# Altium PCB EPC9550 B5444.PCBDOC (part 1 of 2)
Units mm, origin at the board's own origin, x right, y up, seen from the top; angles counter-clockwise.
Board outline 50 x 37 mm, 8 copper layers (Top Layer, Mid-Layer 1, Mid Layer 2 (Gnd), Mid-Layer 3 (Gnd), Mid-Layer 4 (54V), Mid Layer 5 (54V), Mid-Layer 6, Bottom Layer), stack 1.444 mm thick; 107 components, 61 nets, 523 pads, 597 vias.
Unrouted connection lines stored in the file: 17.
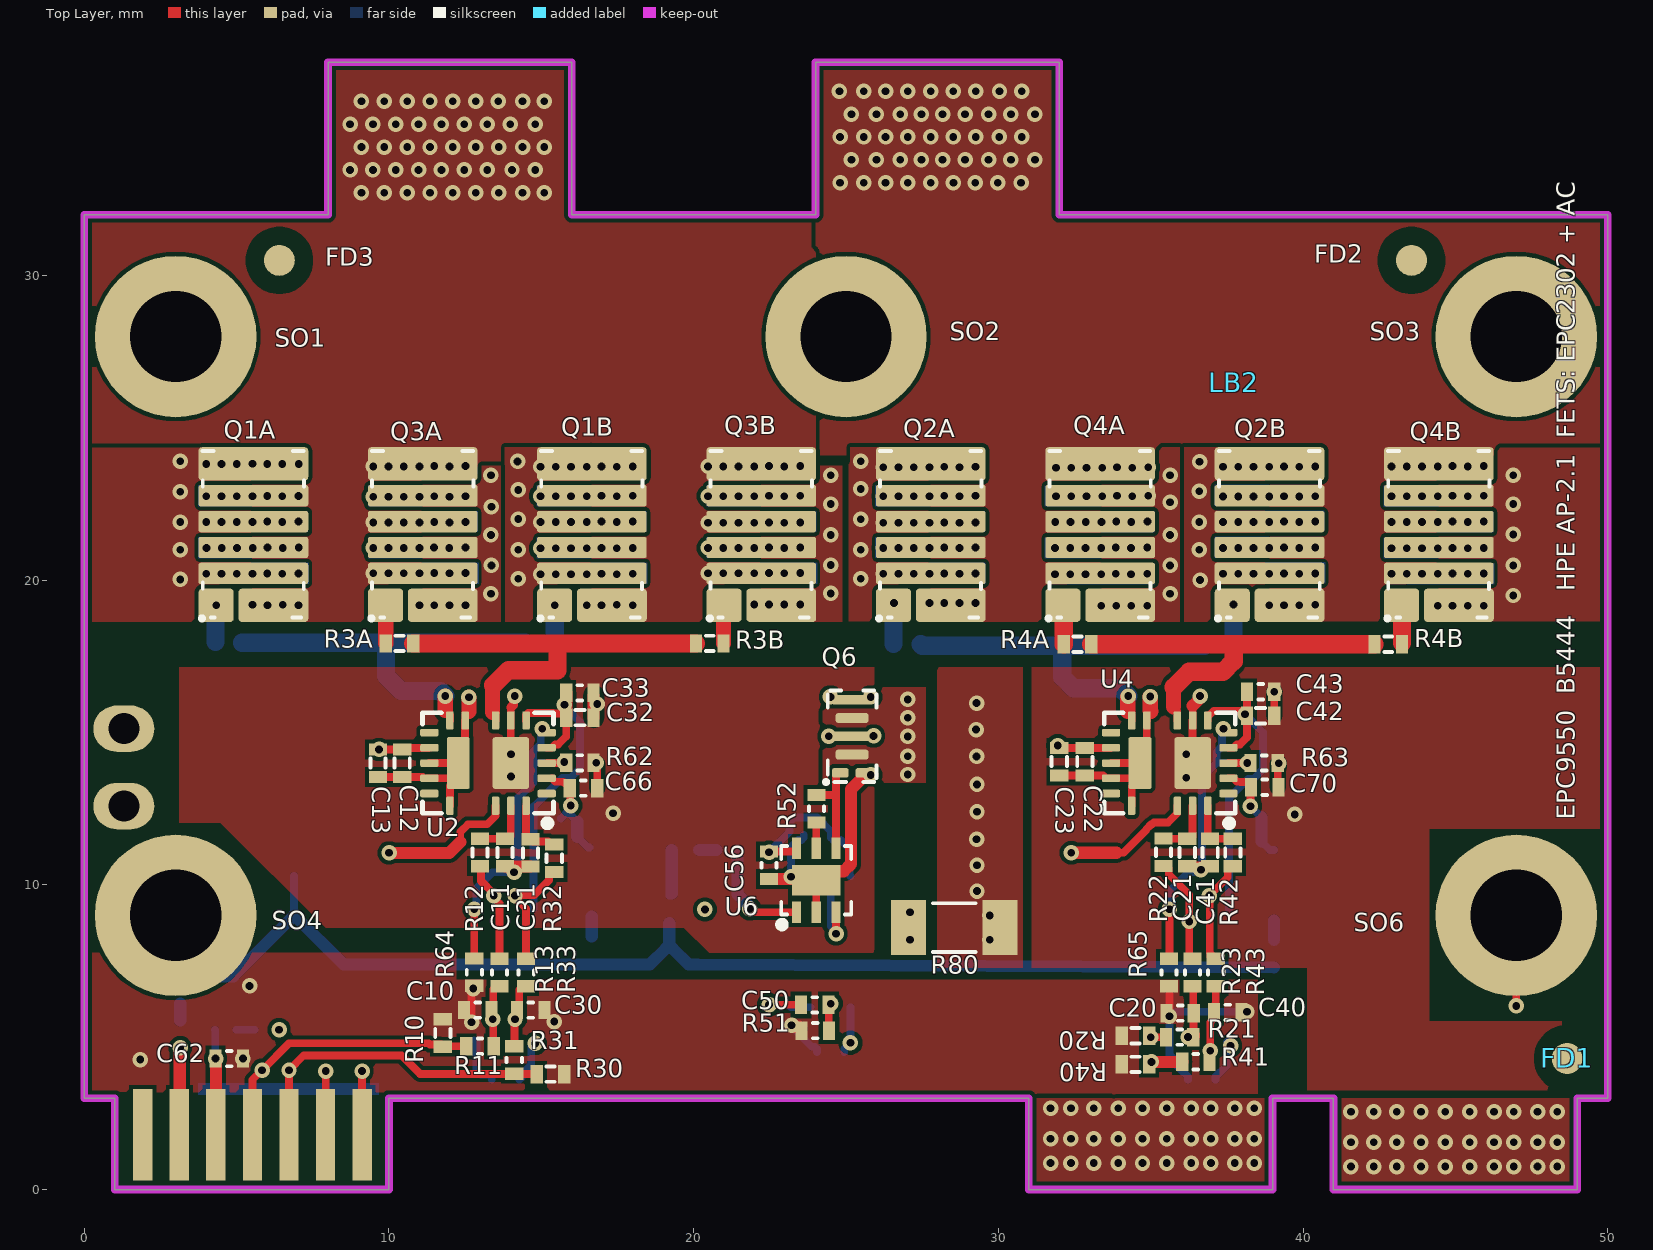
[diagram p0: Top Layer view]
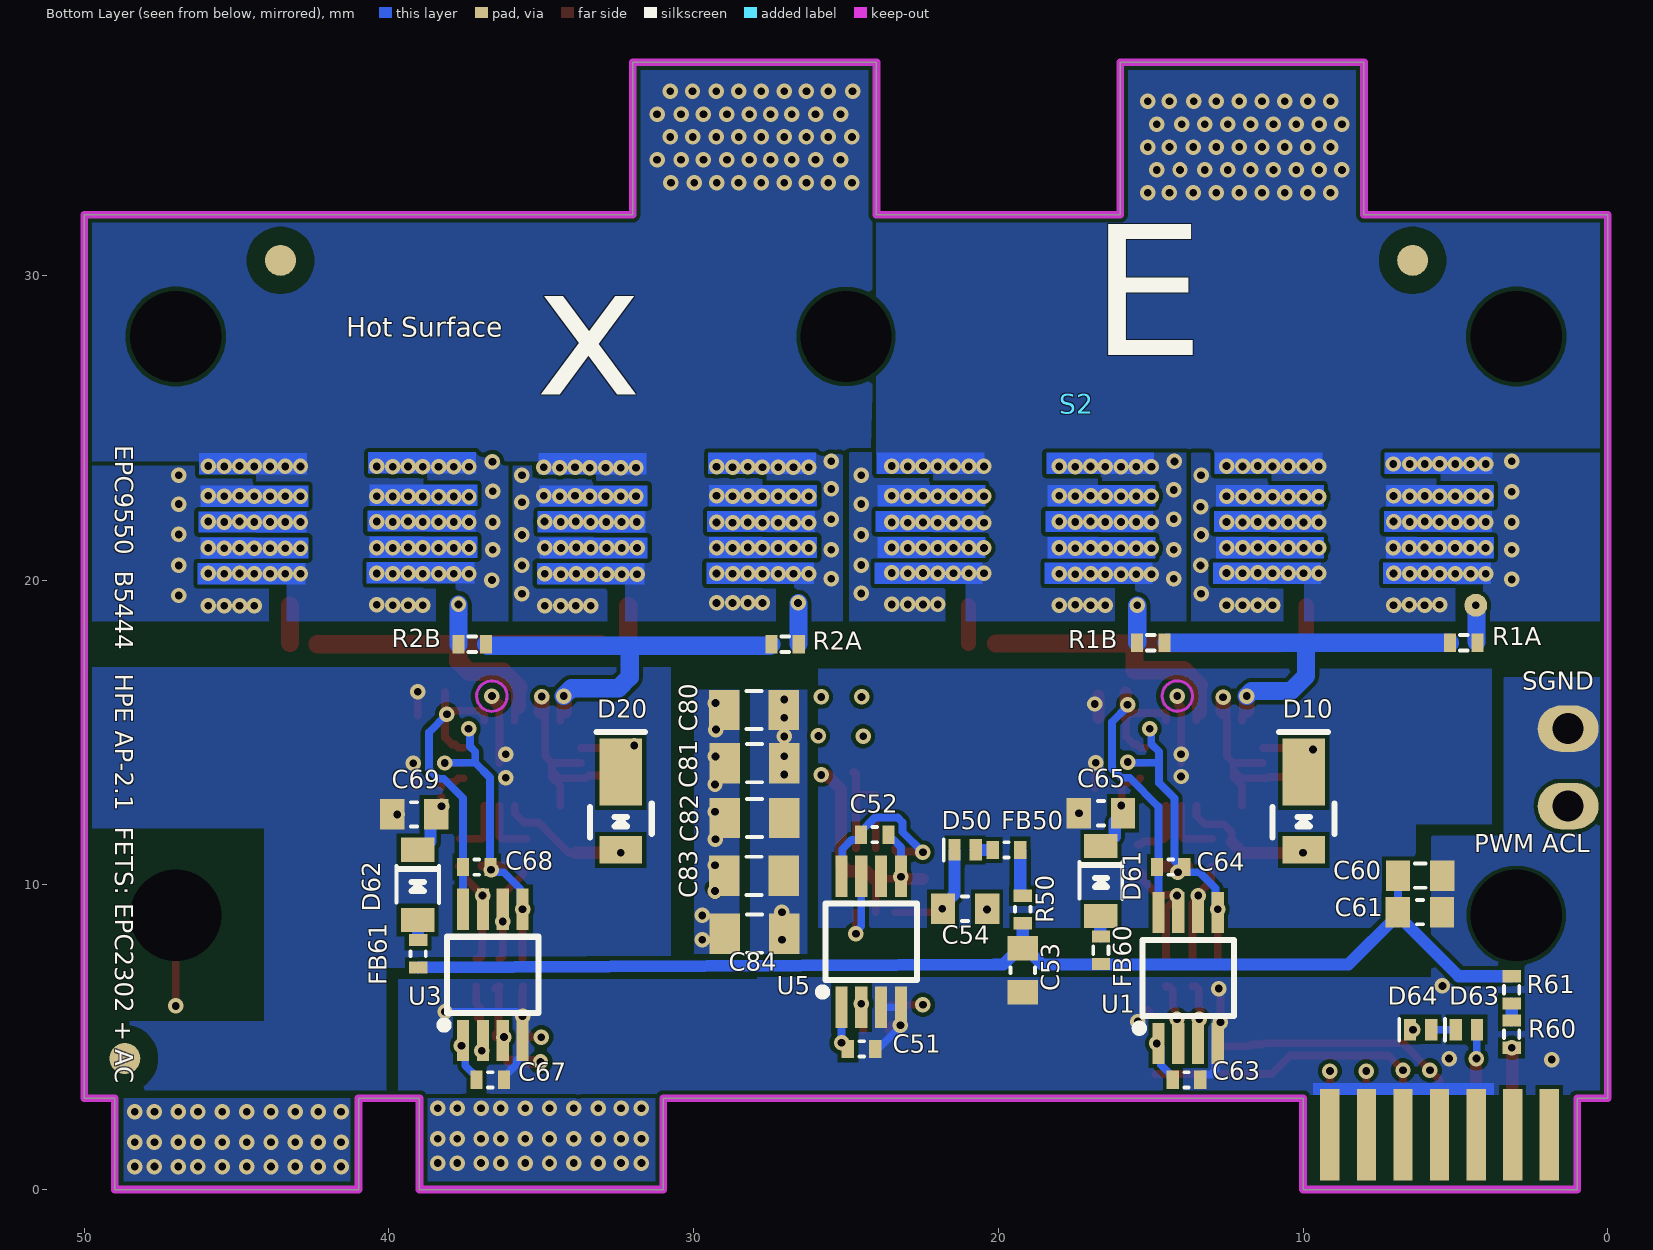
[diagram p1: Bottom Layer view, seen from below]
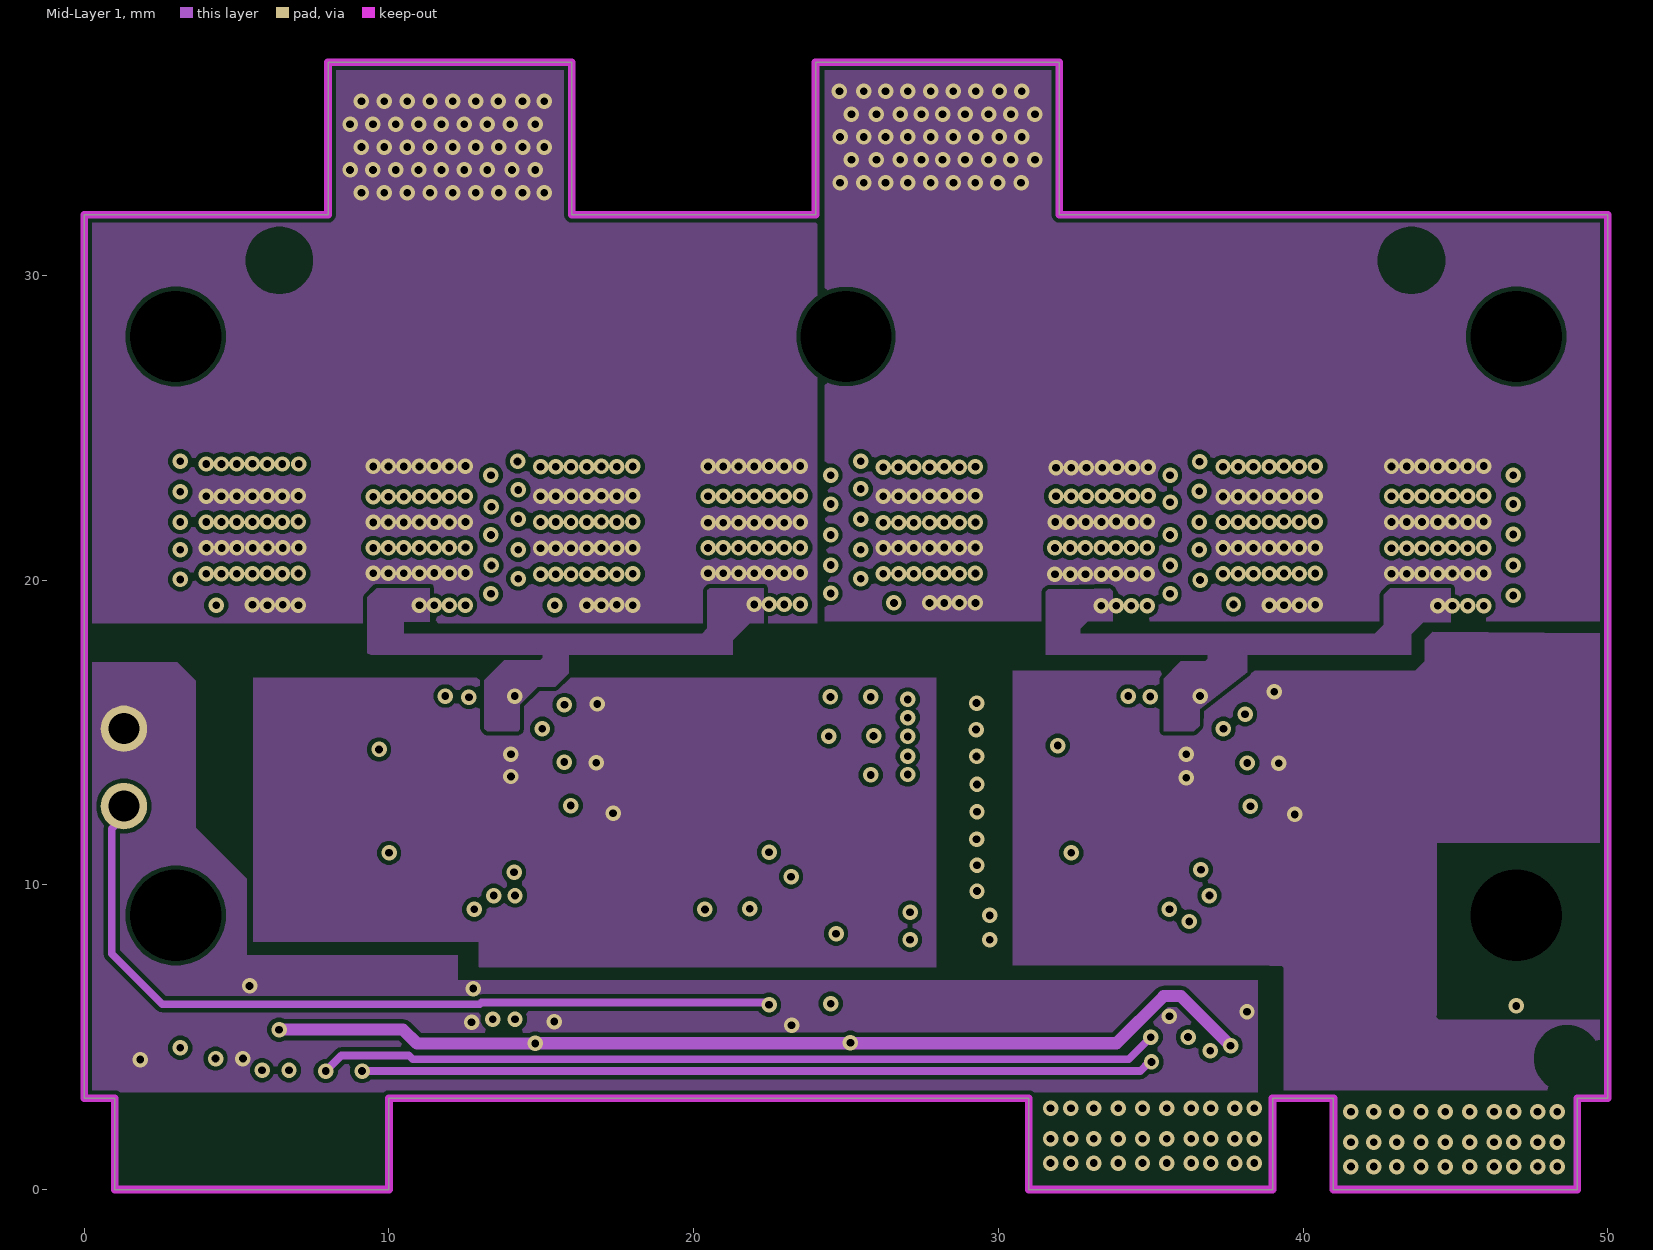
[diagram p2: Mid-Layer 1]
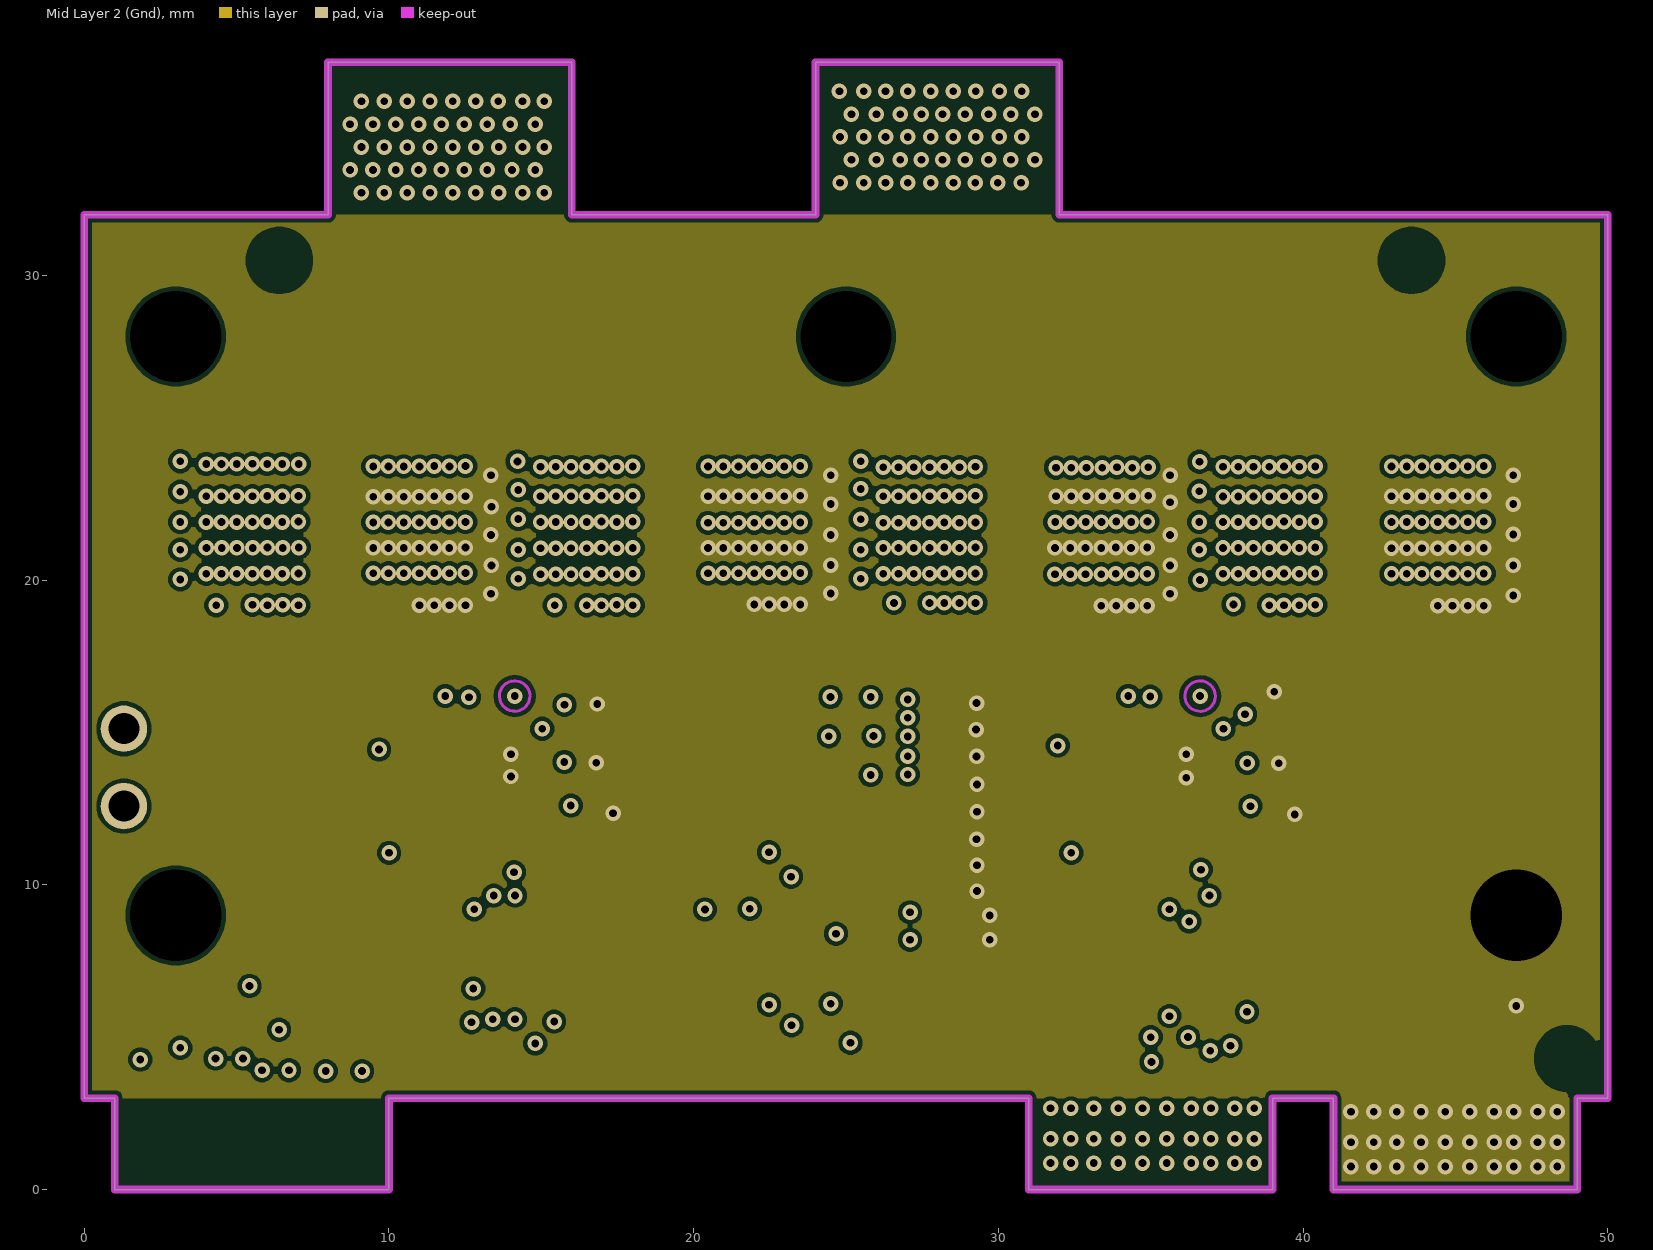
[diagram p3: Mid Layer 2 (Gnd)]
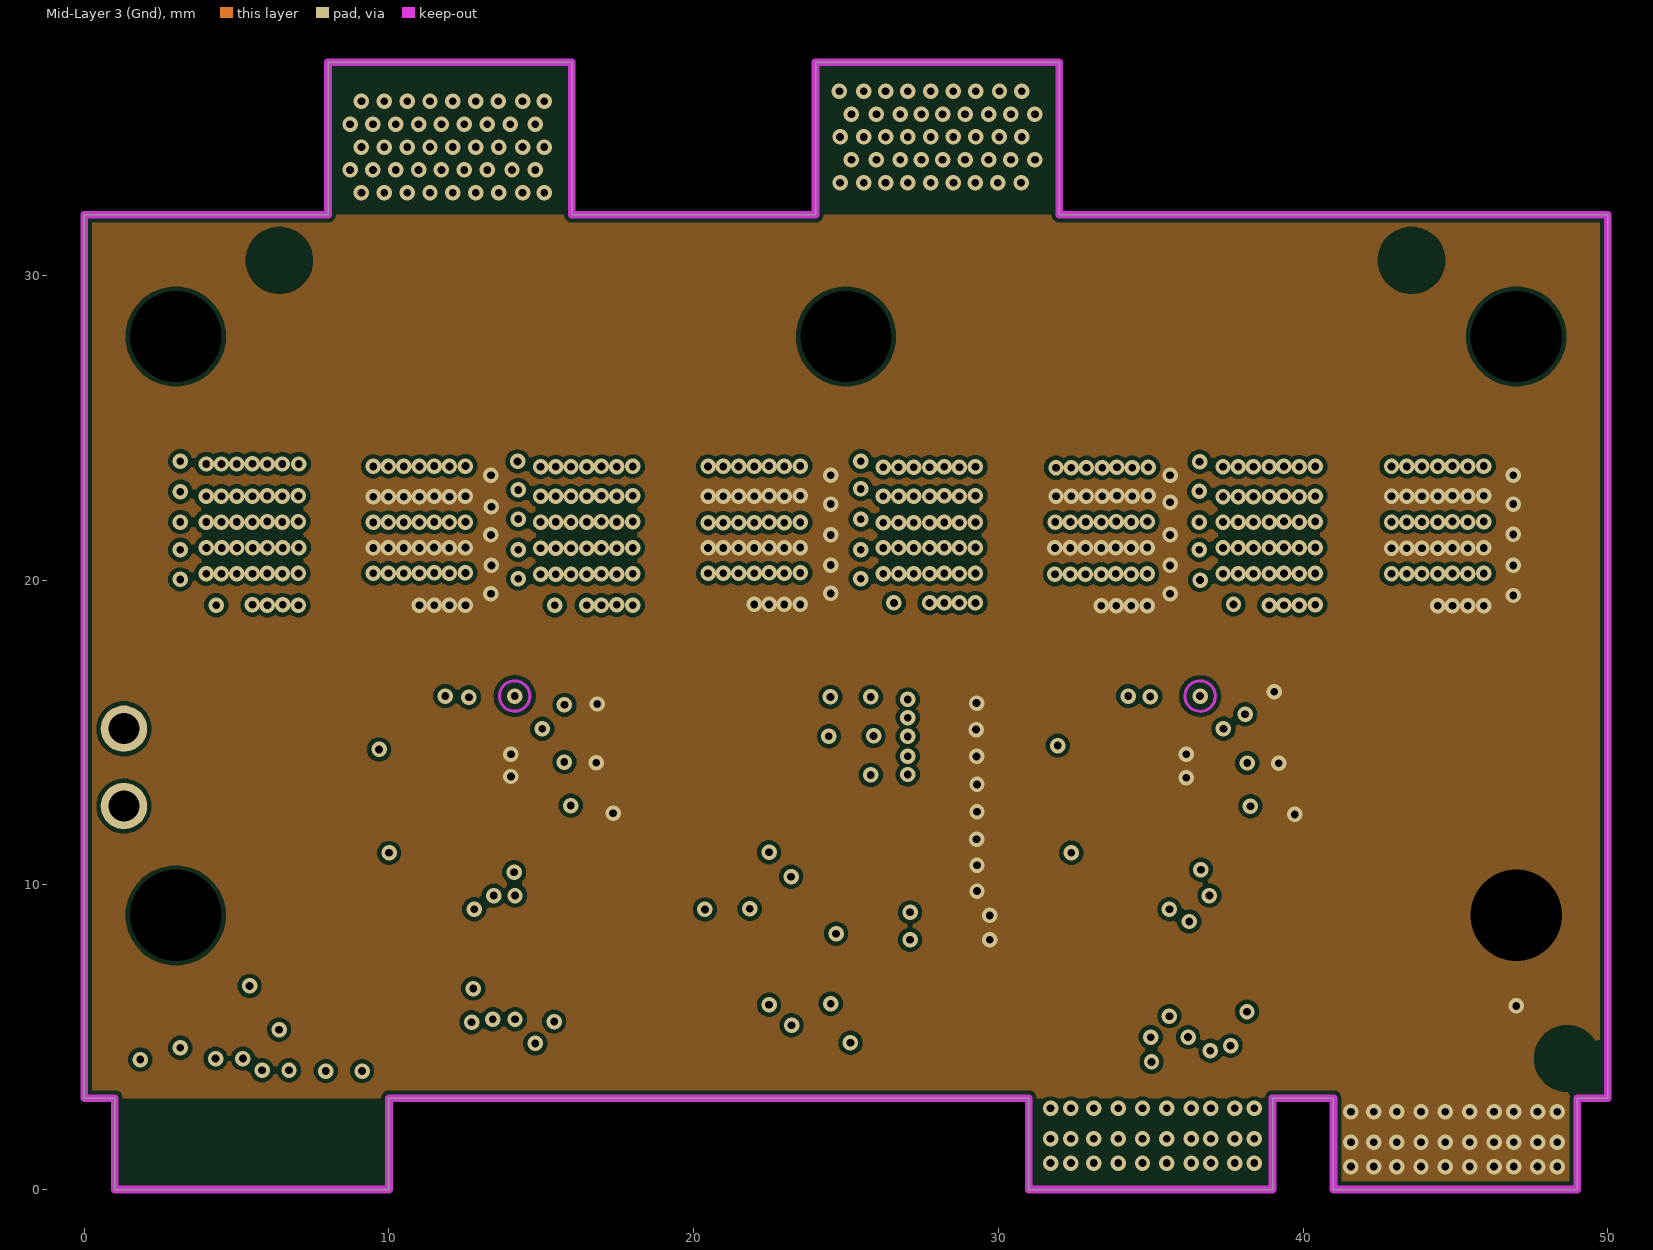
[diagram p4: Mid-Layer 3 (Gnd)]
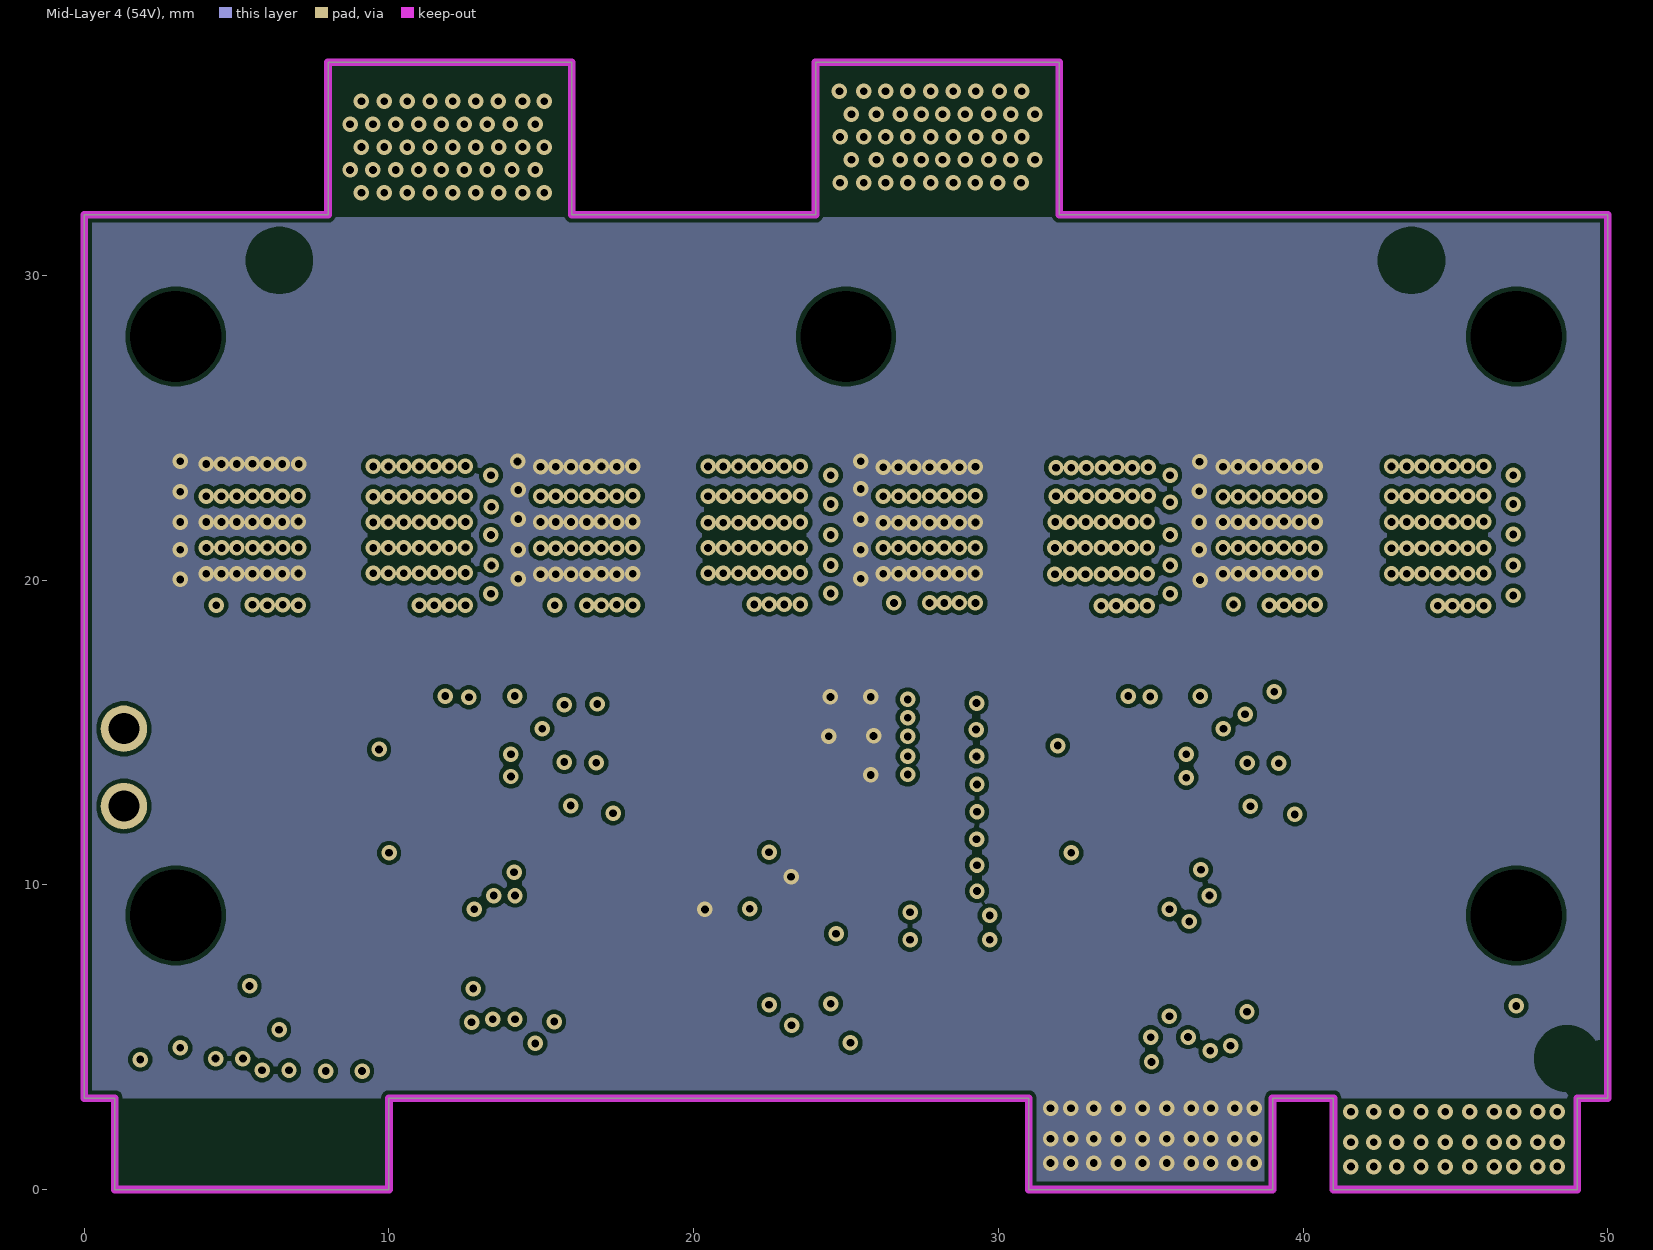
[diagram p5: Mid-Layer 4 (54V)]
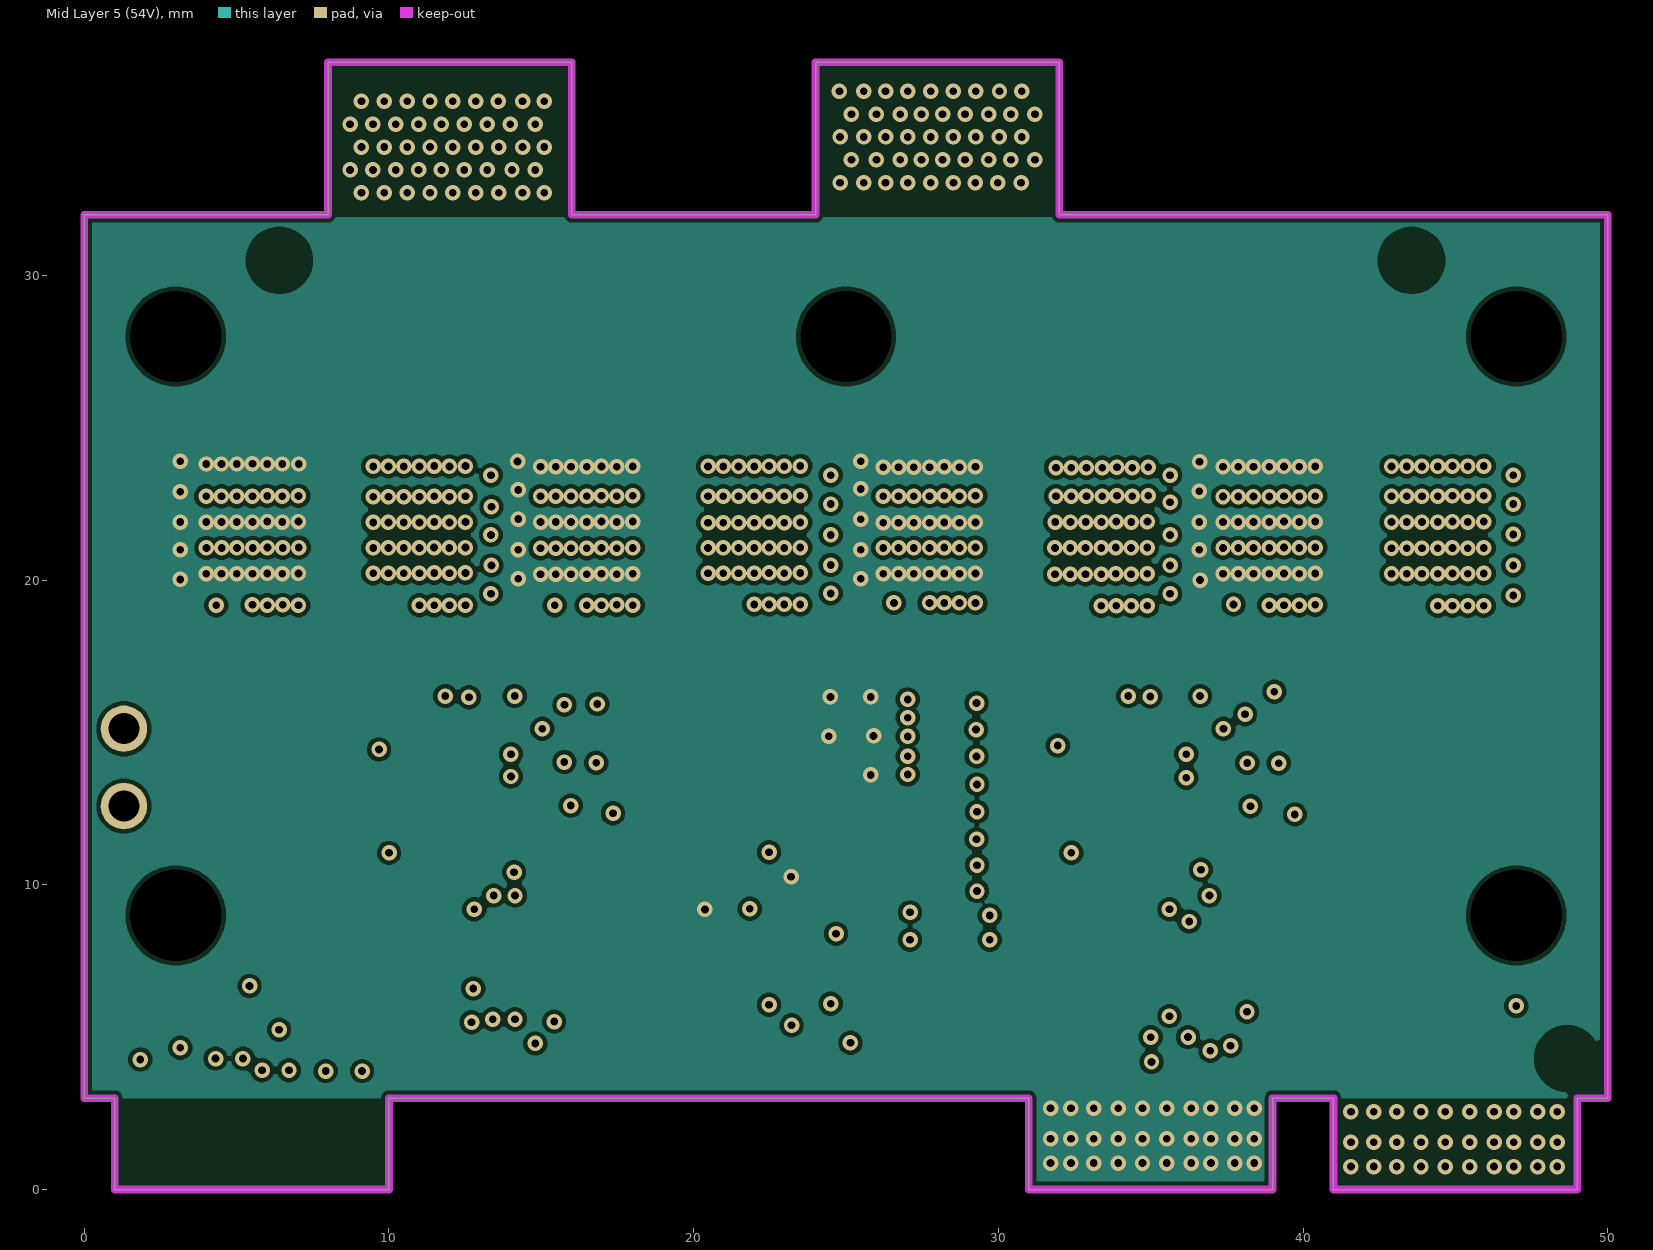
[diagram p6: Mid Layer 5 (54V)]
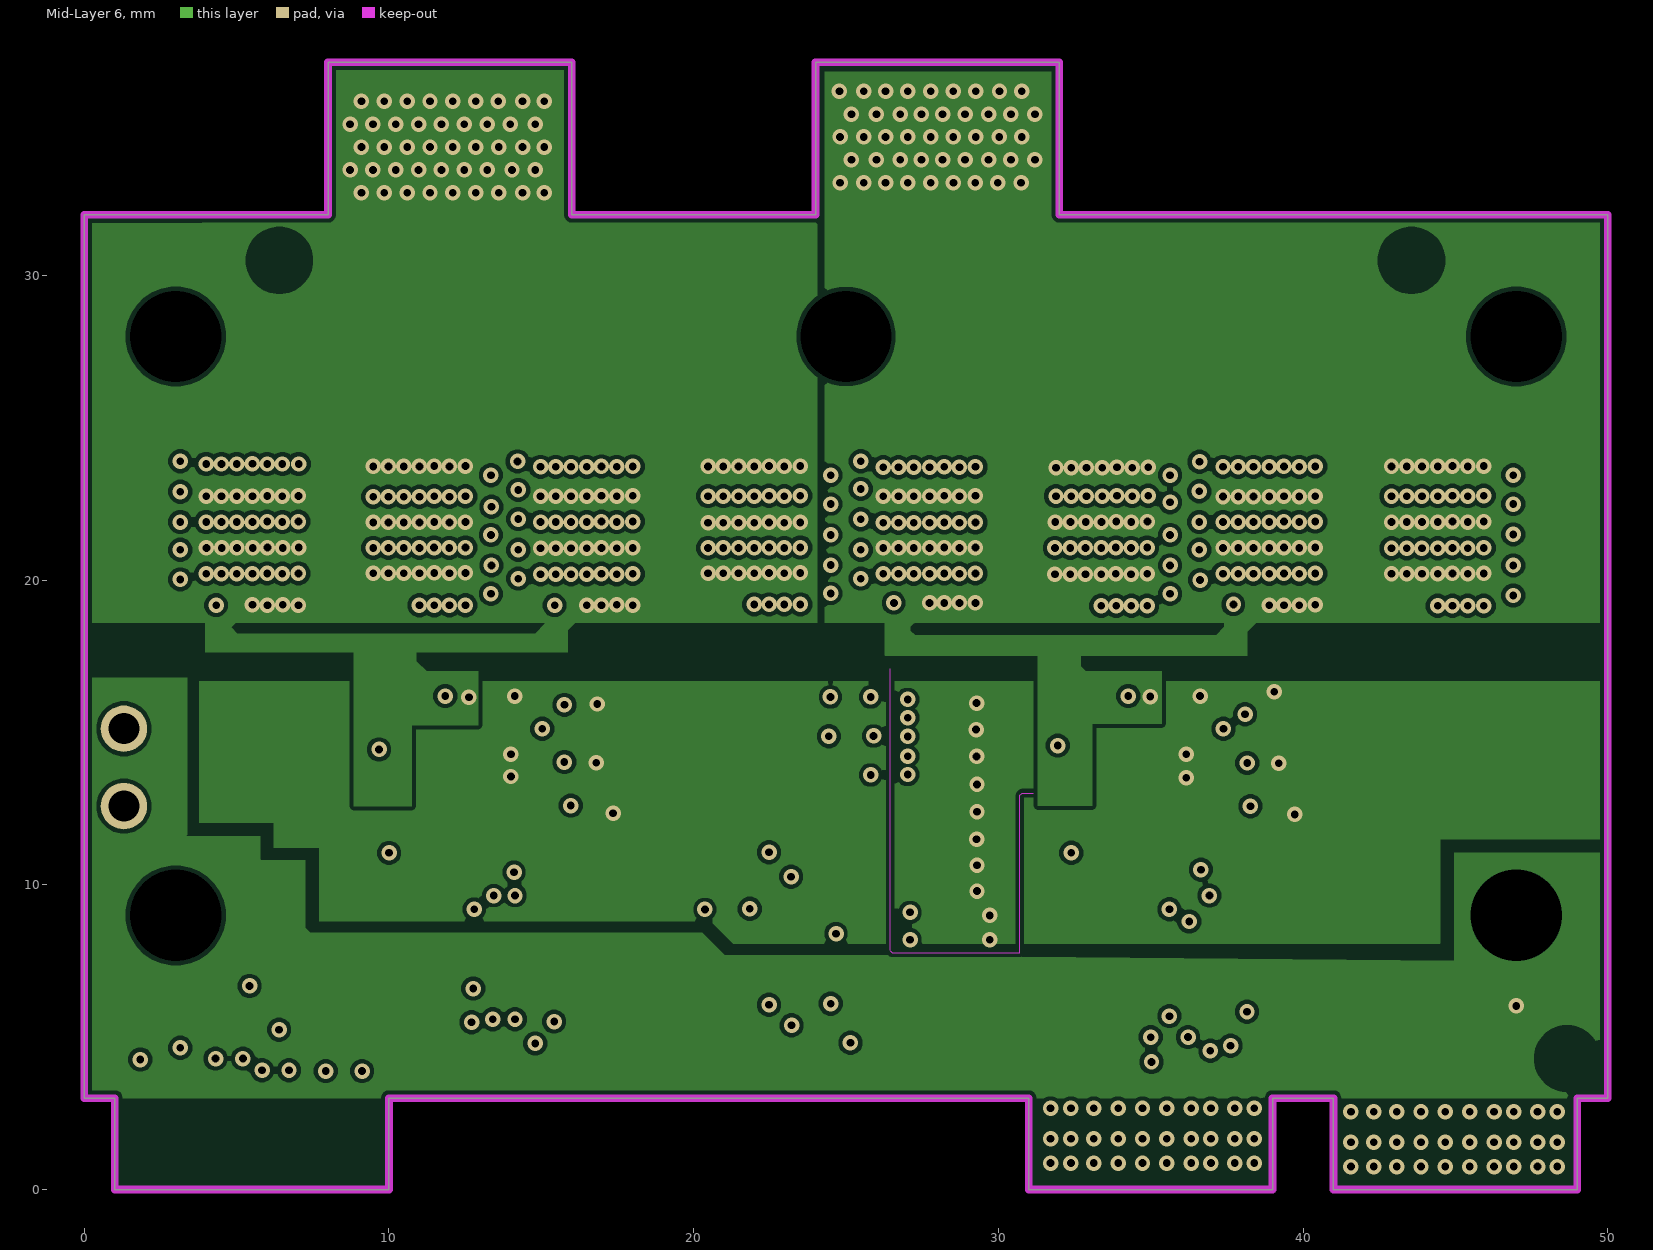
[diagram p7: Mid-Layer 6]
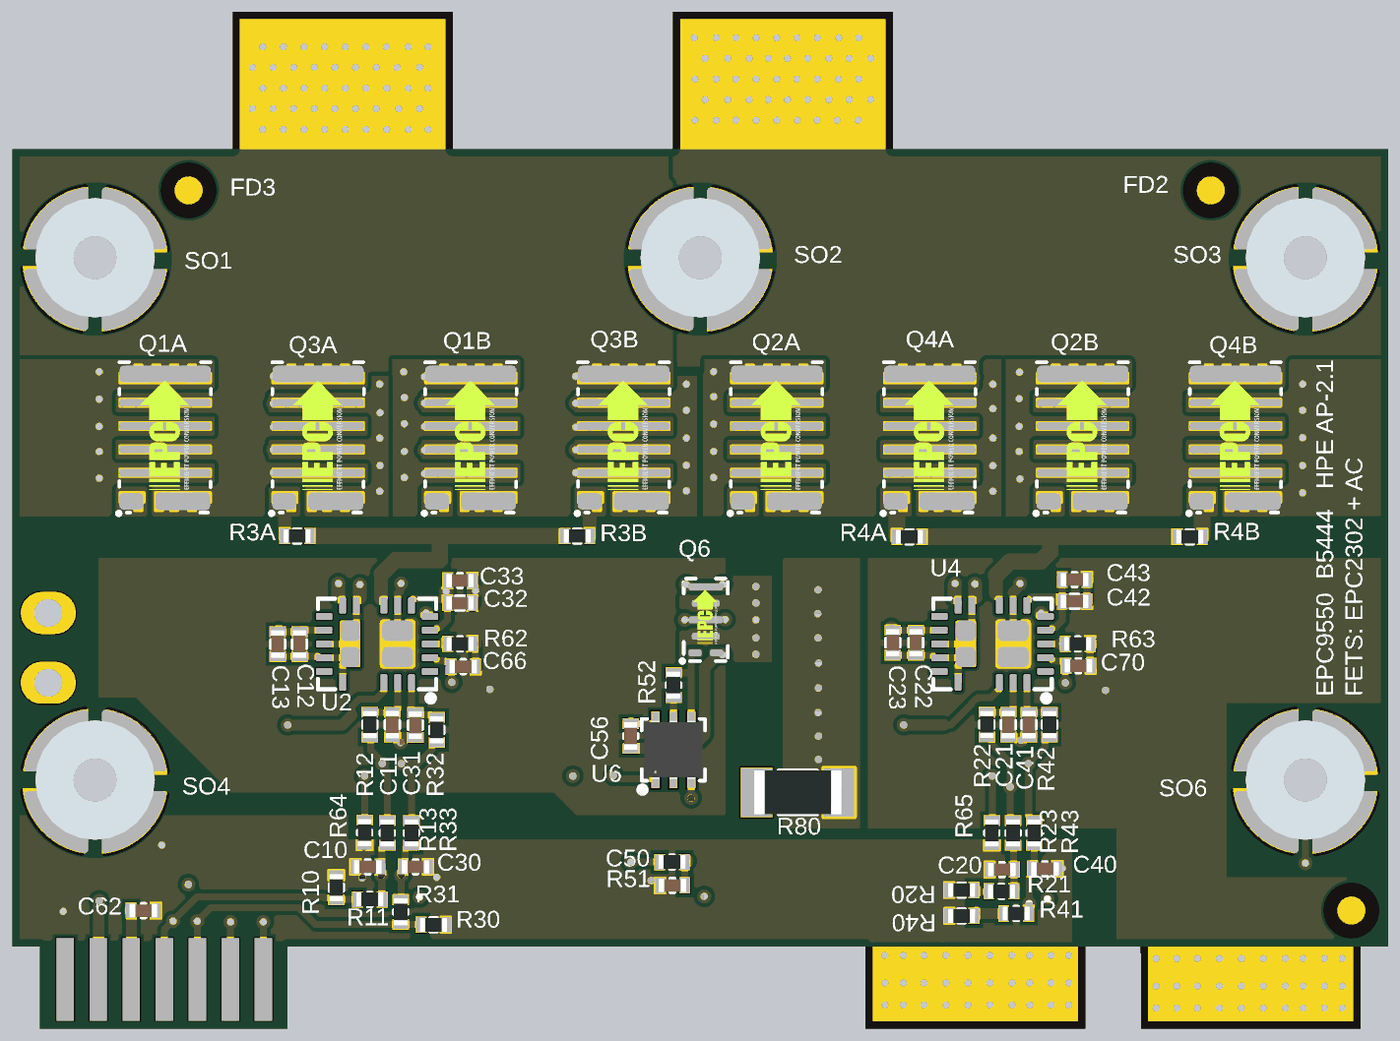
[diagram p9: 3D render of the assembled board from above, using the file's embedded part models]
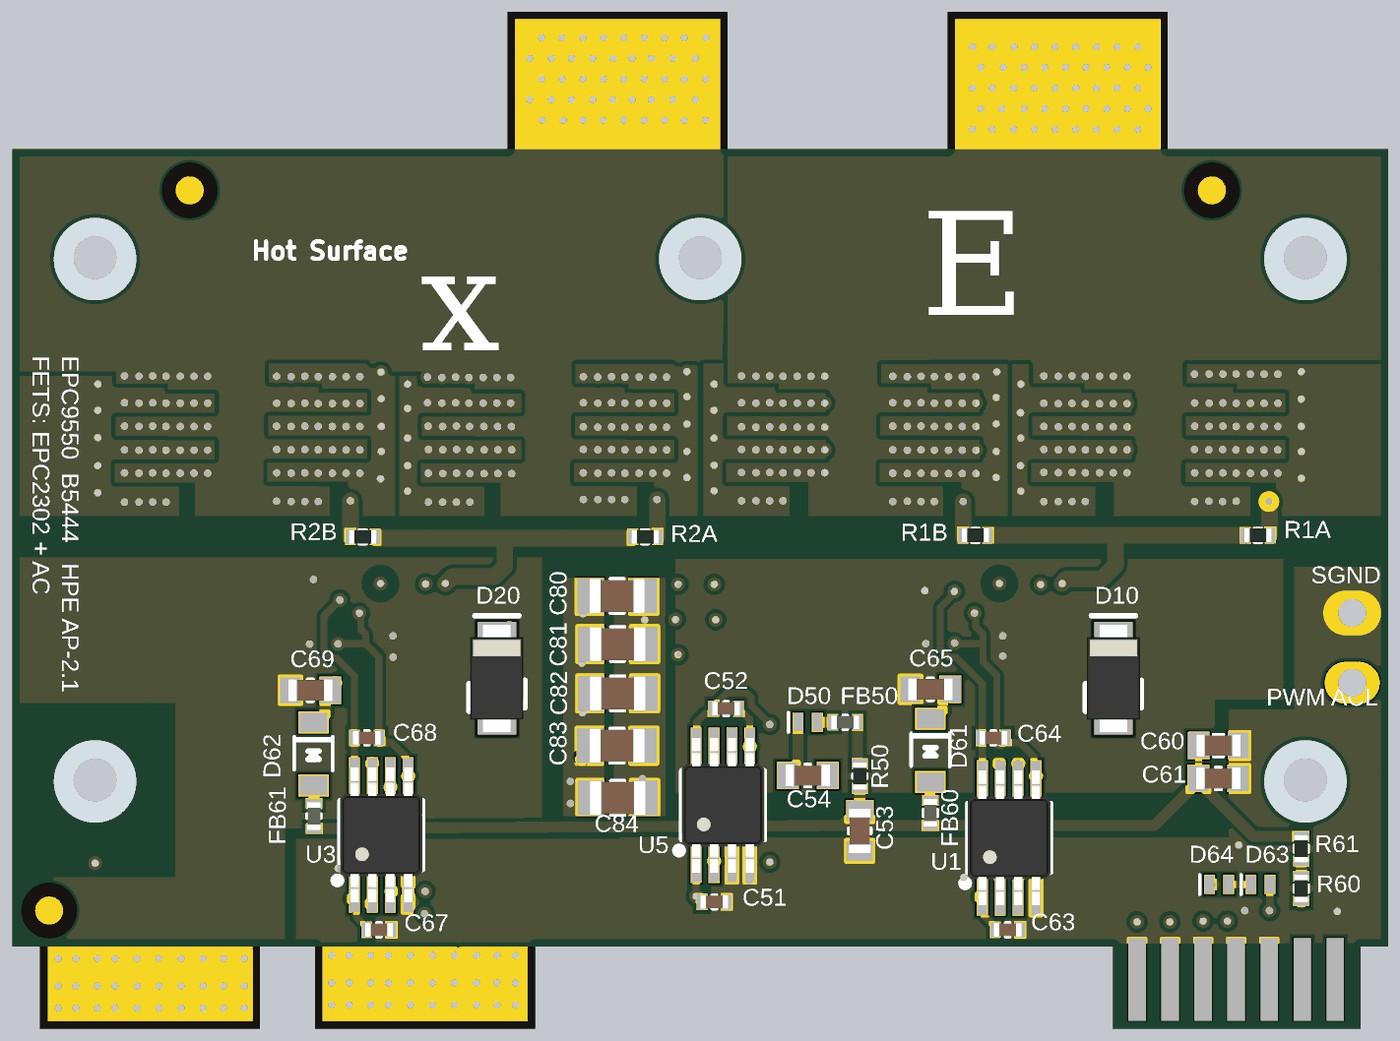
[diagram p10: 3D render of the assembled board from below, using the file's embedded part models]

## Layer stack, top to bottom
Top Solder: solder mask 0.0102, Solder Resist, Dk 3.5
Top Layer: signal copper 0.07
Dielectric 1: prepreg 0.1295, PP-017, Dk 4.3
Mid-Layer 1: signal copper 0.07
Dielectric 6: core 0.1524, Core-018, Dk 4.6
Mid Layer 2 (Gnd): signal copper 0.07
Dielectric 2: prepreg 0.0965, PP-013, Dk 4.3
Mid-Layer 3 (Gnd): signal copper 0.07
Dielectric 3: core 0.127, Core-015, Dk 4.4
Mid-Layer 4 (54V): signal copper 0.07
Dielectric 4: prepreg 0.0965, PP-013, Dk 4.3
Mid Layer 5 (54V): signal copper 0.07
Dielectric 7: core 0.1524, Core-018, Dk 4.6
Mid-Layer 6: signal copper 0.07
Dielectric 5: prepreg 0.1295, PP-017, Dk 4.3
Bottom Layer: signal copper 0.07
Bottom Solder: solder mask 0.0102, Solder Resist, Dk 3.5

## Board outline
39,0 39,3 41,3 41,0 49,0 49,3 50,3 50,32 32,32 32,37 24,37 24,32 16,32 16,37 8,37 8,32 0,32 0,3 1,3 1,0 10,0 10,3 31,3 31,0

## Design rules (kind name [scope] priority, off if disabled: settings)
AssemblyTestPointUsage [All] p1 off:
AssemblyTestpoint [All] p1 off: testpointundercomponent=TRUE minsize=1.016 maxsize=2.54 preferedsize=1.524 minholesize=0 maxholesize=1.016 preferedholesize=0.813 testpointgrid=0.025 usegrid=TRUE gridtolerance=0 allowsidetop=TRUE allowsidebottom=TRUE
Clearance [All] p1: gap=0.135 ignorepadtopadclearanceinfootprint=TRUE // Everything else
Clearance Keepout [(OnLayer('Keep-Out Layer'))] p2: gap=0.508 ignorepadtopadclearanceinfootprint=TRUE except(0: Arc-Hole Track-Hole SMDPad-Hole THPad-Hole Via-Hole Fill-Hole Poly-Hole Region-Hole Text-Hole)
ComponentClearance [All] p1: gap=0.127 collisioncheckmode=3 verticalgap=0 showdistances=FALSE
FabricationTestPointUsage [All] p1 off: valid=0 allowmultiple=FALSE
FabricationTestpoint [All] p1 off: side=3 testpointundercomponent=TRUE minsize=1.016 maxsize=2.54 preferedsize=1.524 minholesize=0 maxholesize=1.016 preferedholesize=0.813 testpointgrid=0.025 allowsidetop=TRUE allowsidebottom=TRUE usegrid=TRUE gridtolerance=0
FanoutControl Fanout_BGA [IsBGA] p1 off: bgadir=Out bgaviamode=Centered fanoutstyle=Auto fanoutdirection=Alternating viagrid=0.025 // Fanout_BGA (Default Rule)
FanoutControl Fanout_LCC [IsLCC] p2 off: bgadir=Out bgaviamode=Centered fanoutstyle=Auto fanoutdirection=Alternating viagrid=0.025 // Fanout_LCC (Default Rule)
FanoutControl Fanout_SOIC [IsSOIC] p3 off: bgadir=Out bgaviamode=Centered fanoutstyle=Auto fanoutdirection=Alternating viagrid=0.025 // Fanout_SOIC (Default Rule)
FanoutControl Fanout_Small [(CompPinCount < 5)] p4 off: bgadir=Out bgaviamode=Centered fanoutstyle=Auto fanoutdirection=OutThenIn viagrid=0.025 // Fanout_Small (Default Rule)
FanoutControl Fanout_Default [All] p5 off: bgadir=Out bgaviamode=Centered fanoutstyle=Auto fanoutdirection=Alternating viagrid=0.025 // Fanout_Default (Default Rule)
HoleSize [All] p1: absolutevalues=TRUE maxlimit=3 minlimit=0.025 maxpercent=80.000 minpercent=20.000
HoleToHoleClearance [All] p1 off: gap=0.254 allowstackedmicrovias=TRUE
MinimumSolderMaskSliver [All] p1: minsoldermaskwidth=0.02
NetAntennae [All] p1 off: netantennaetolerance=0
PlaneConnect [All] p1: planeconnectstyle=Direct reliefexpansion=0.508 reliefentries=4 reliefconductorwidth=0.254 reliefairgap=0.254
PolygonConnect [All] p1: connectstyle=Direct reliefconductorwidth=0.254 reliefentries=4 polygonreliefangle="90 Angle" airgapwidth=0.254
RoomDefinition "EPC9550 B5444" [InComponentClass('EPC9550 B5444')] p1: confinementstyle=ConfineIn formatcopy=TRUE lockcomponents=FALSE outline 0,-0.3 50.35,-0.3 50.35,37 0,37
RoutingVias [All] p1: holewidth=0.711 width=1.27 viastyle="Through Hole" minholewidth=0.203 minwidth=0.254 maxholewidth=1.27 maxwidth=2.54
SilkToSilkClearance [All] p1: silktosilkclearance=0.025
SilkToSolderMaskClearance SilkscreenOverComponentPads [IsPad OR IsVia OR OnLayer('Top Solder') vs OnLayer('Top Overlay')] p1: minsilkscreentomaskgap=0.025 clearancetoexposedcopper=TRUE
SilkToSolderMaskClearance SilkscreenOverComponentPads_1 [IsPad OR IsVia OR OnLayer('Bottom Solder') vs OnLayer('Bottom Overlay')] p2: minsilkscreentomaskgap=0.025 clearancetoexposedcopper=TRUE
SolderMaskExpansion [All] p1: expansion=0.051 istentingtop=FALSE
Width [All] p1: maxlimit=254 minlimit=0.127 preferedwidth=0.254
13 further rules are at their usual default settings.

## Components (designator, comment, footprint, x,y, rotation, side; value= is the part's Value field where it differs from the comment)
C10 "EMPTY" CC0402 12.913,5.892 r180 top value=TBD
C11 "C1005C0G2A221J050BA" CC0402 13.807,11.066 r270 top value=220pF
C12 "C1005X5R1E474K050BB" CC0402 10.431,13.996 r270 top value=470nF
C13 "C1005X5R1E105K050BC" CC0402 9.641,13.996 r270 top value=1uF
C20 "EMPTY" CC0402 35.967,5.792 r180 top value=TBD
C21 "C1005C0G2A221J050BA" CC0402 36.2,11.066 r270 top value=220pF
C22 "C1005X5R1E474K050BB" CC0402 32.84,14.045 r270 top value=470nF
C23 "C1005X5R1E105K050BC" CC0402 32,14.045 r270 top value=1uF
C30 "EMPTY" CC0402 14.653,5.892 r0 top value=TBD
C31 "C1005C0G2A221J050BA" CC0402 14.644,11.05 r270 top value=220pF
C32 "GRM155R61E225ME15D" CC0402 16.267,15.49 r0 top value=2.2uF
C33 "GRM155R61E225ME15D" CC0402 16.267,16.305 r0 top value=2.2uF
C40 "EMPTY" CC0402 37.532,5.819 r0 top value=TBD
C41 "C1005C0G2A221J050BA" CC0402 36.95,11.066 r270 top value=220pF
C42 "GRM155R61E225ME15D" CC0402 38.608,15.551 r0 top value=2.2uF
C43 "GRM155R61E225ME15D" CC0402 38.608,16.341 r0 top value=2.2uF
C50 "CC0402JRNPO9BN470" CC0402 23.988,5.218 r180 top value=47pF
C51 "GRM155R61E225ME15D" CC0402 24.489,4.618 r180 bottom value=2.2uF
C52 "GRM155R61E225ME15D" CC0402 24.06,11.65 r180 bottom value=2.2uF
C53 "C1608X5R1E106M080AC" CC0603 19.2,7.2 r90 bottom value=10uF
C54 "C1608X5R1E106M080AC" CC0603 21.093,9.216 r0 bottom value=10uF
C56 "GRM155R61E225ME15D" CC0402 22.474,10.65 r90 top value=2.2uF
C60 "C1608X5R1E106M080AC" CC0603 6.158,10.306 r0 bottom value=10uF
C61 "C1608X5R1E106M080AC" CC0603 6.165,9.108 r180 bottom value=10uF
C62 "GRM155R61E225ME15D" CC0402 4.756,4.3 r0 top value=2.2uF
C63 "GRM155R61E225ME15D" CC0402 13.823,3.602 r180 bottom value=2.2uF
C64 "GRM155R61E225ME15D" CC0402 14.346,10.585 r180 bottom value=2.2uF
C65 "C1608X5R1E106M080AC" CC0603 16.633,12.35 r180 bottom value=10uF
C66 "GRM155R61E225ME15D" CC0402 16.383,13.176 r0 top value=2.2uF
C67 "GRM155R61E225ME15D" CC0402 36.678,3.602 r180 bottom value=2.2uF
C68 "GRM155R61E225ME15D" CC0402 37.119,10.585 r180 bottom value=2.2uF
C69 "C1608X5R1E106M080AC" CC0603 39.174,12.315 r180 bottom value=10uF
C70 "GRM155R61E225ME15D" CC0402 38.747,13.206 r0 top value=2.2uF
C80 "08051C105K4Z2A" CC0805 28.022,15.746 r0 bottom value=1uF
C81 "08051C105K4Z2A" CC0805 28,13.996 r0 bottom value=1uF
C82 "08051C105K4Z2A" CC0805 28,12.2 r0 bottom value=1uF
C83 "08051C105K4Z2A" CC0805 28.025,10.3 r0 bottom value=1uF
C84 "08051C105K4Z2A" CC0805 28,8.4 r0 bottom value=1uF
D10 "Diode Schottky" POWERDI-123 9.981,12.425 r270 bottom
D20 "Diode Schottky" POWERDI-123 32.393,12.425 r270 bottom
D50 "Diode" DFN1006-2 21.093,11.15 r180 bottom
D61 "Diode" "TUMD2SM ROHM" 16.633,10.13 r90 bottom
D62 "Diode" "TUMD2SM ROHM" 39.06,10 r90 bottom
D63 "Diode" DFN1006-2 4.636,5.25 r180 bottom
D64 "Diode" DFN1006-2 6.142,5.25 r180 bottom
FB50 "MMZ1005Y182CTD25" LC0402sml 19.732,11.15 r0 bottom value="1.8kE @ 100MHz"
FB60 "MMZ1005Y182CTD25" LC0402sml 16.633,7.855 r90 bottom value="1.8kE @ 100MHz"
FB61 "MMZ1005Y182CTD25" LC0402sml 39.044,7.74 r90 bottom value="1.8kE @ 100MHz"
FD1 "PCB Fiducial" Fiducial_Board 48.669,4.303 r0 top locked value="Fiducial 40mil"
FD2 "PCB Fiducial" Fiducial_Board 43.561,30.5 r0 top value="Fiducial 40mil"
FD3 "PCB Fiducial" Fiducial_Board 6.4,30.5 r0 top value="Fiducial 40mil"
LB2 "Hot_SIGN" Hot_SIGN 37.725,26.505 r0 top
Q1A "EPC2302" D0606_100V 5.55,21.5 r90 top locked
Q1B "EPC2302" D0606_100V 16.66,21.5 r90 top locked
Q2A "EPC2302" D0606_100V 27.78,21.5 r90 top locked
Q2B "EPC2302" D0606_100V 38.9,21.5 r90 top locked
Q3A "EPC2302" D0606_100V 11.11,21.5 r90 top locked
Q3B "EPC2302" D0606_100V 22.22,21.5 r90 top locked
Q4A "EPC2302" D0606_100V 33.34,21.5 r90 top locked
Q4B "EPC2302" D0606_100V 44.46,21.5 r90 top locked
Q6 "EPC2059" D0298T34M 25.2,14.879 r90 top
R1A "RMCF0402FT2R0" RC0402 4.728,17.95 r180 bottom value=2.2
R1B "RMCF0402FT2R0" RC0402 14.996,17.95 r0 bottom value=2.2
R2A "RMCF0402FT2R0" RC0402 27,17.9 r180 bottom value=2.2
R2B "RMCF0402FT2R0" RC0402 37.269,17.9 r0 bottom value=2.2
R3A "RMCF0402FT2R0" RC0402 10.346,17.927 r180 top value=2.2
R3B "RMCF0402FT2R0" RC0402 20.529,17.927 r0 top value=2.2
R4A "RMCF0402FT2R0" RC0402 32.6,17.9 r180 top value=2.2
R4B "RMCF0402FT2R0" RC0402 42.797,17.9 r0 top value=2.2
R10 "ERJ-2RKF1002X" RC0402 11.768,5.14 r90 top value=10k
R11 "ERJ-2GE0R00X" RC0402 12.988,4.705 r0 top value=0E
R12 "RC0402FR-07100RL" RC0402 12.988,11.066 r90 top value=100E
R13 "EMPTY" RC0402 13.625,7.126 r90 top value=0E
R20 "ERJ-2RKF1002X" RC0402 34.501,5.049 r180 top value=10k
R21 "ERJ-2GE0R00X" RC0402 35.95,5.005 r0 top value=0E
R22 "RC0402FR-07100RL" RC0402 35.42,11.072 r90 top value=100E
R23 "EMPTY" RC0402 36.373,7.126 r90 top value=0E
R30 "ERJ-2RKF1002X" RC0402 15.303,3.789 r0 top value=10k
R31 "ERJ-2GE0R00X" RC0402 14.11,4.255 r90 top value=0E
R32 "RC0402FR-07100RL" RC0402 15.425,10.874 r90 top value=100E
R33 "EMPTY" RC0402 14.5,7.126 r90 top value=0E
R40 "ERJ-2RKF1002X" RC0402 34.501,4.112 r180 top value=10k
R41 "ERJ-2GE0R00X" RC0402 36.484,4.195 r0 top value=0E
R42 "RC0402FR-07100RL" RC0402 37.698,11.066 r90 top value=100E
R43 "EMPTY" RC0402 37.135,7.126 r90 top value=0E
R50 "RMCF0402FT2R0" RC0402 19.2,9.195 r90 bottom value=2.2
R51 "RMCF0402FT2R0" RC0402 23.973,6.065 r0 top value=2.2
R52 "ERJ-U02J5R6X" RC0402 24.03,12.502 r270 top value=5.6
R60 "RMCF0402FT2R0" RC0402 3.15,5.105 r90 bottom value=2.2
R61 "RMCF0402FT2R0" RC0402 3.15,6.553 r90 bottom value=2.2
R62 "ERJ-2GE0R00X" RC0402 16.267,14.007 r0 top value=0E
R63 "ERJ-2GE0R00X" RC0402 38.724,14 r0 top value=0E
R64 "EMPTY" RC0402 12.801,7.138 r90 top value=0E
R65 "EMPTY" RC0402 35.602,7.126 r90 top value=0E
R80 "TBD" RC1206 28.548,8.6 r0 top value=200K
S2 "AntiStat_Sign" AS_SIGN 17.431,25.8 r180 bottom
SO1 "EPC_Thermal_Spacer_SMD_M2" 9774010243R 3,28 r0 top locked value="Round Standoff M2x0.4  1.00mm"
SO2 "EPC_Thermal_Spacer_SMD_M2" 9774010243R 25,28 r0 top locked value="Round Standoff M2x0.4  1.00mm"
SO3 "EPC_Thermal_Spacer_SMD_M2" 9774010243R 47,28 r0 top locked value="Round Standoff M2x0.4  1.00mm"
SO4 "EPC_Thermal_Spacer_SMD_M2" 9774010243R 3,9 r0 top value="Round Standoff M2x0.4  1.00mm"
SO6 "EPC_Thermal_Spacer_SMD_M2" 9774010243R 47,9 r0 top value="Round Standoff M2x0.4  1.00mm"
U1 "IL711-1" MSOP8 13.771,6.946 r180 bottom
U2 "LMG1210RVR" WQFN-19 13.25,14 r90 top locked
U3 "IL711-1" MSOP8 36.594,7.05 r180 bottom locked
U4 "LMG1210RVR" WQFN-19 35.626,14 r90 top locked
U5 "IL711-1" MSOP8 24.171,8.135 r180 bottom locked
U6 "UCC27611DRV" 6-WDFN 24.023,10.15 r90 top

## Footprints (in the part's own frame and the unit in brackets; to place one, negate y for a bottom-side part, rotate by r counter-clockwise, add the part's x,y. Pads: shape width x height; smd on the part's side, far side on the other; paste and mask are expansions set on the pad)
6-WDFN [mm]
  rect 0.7x0.3 smd paste-0.025 mask+0.07: 1(-1.05,0.65) 2(-1.05,0) 3(-1.05,-0.65) 4(1.05,-0.65) 5(1.05,0) 6(1.05,0.65)
  rect 1x1.6 smd paste-0.1 mask+0.07: EP(0,0)
  silkscreen extent -1.54,-1.15 1.12,1.22, body extent -1.05,-1.05 1.05,1.05, height 0.81
9774010243R [mm]
  round 5.3 / inner round 0 / far side round 0 hole 3 unplated mask-2: 1(0,0)
  body extent -2.17,-2.12 2.18,2.22, height 1
AS_SIGN [mm]
CC0402 [mm] "Size 0402 Ceramic capacitor compact"
  rect 0.4x0.6 smd paste-0.025 mask+0.025: 1(-0.45,0) 2(0.45,0)
  silkscreen extent -0.08,-0.25 0.08,0.25, body extent -0.5,-0.25 0.5,0.25, height 0.53
CC0603 [mm] "Size 0402 Ceramic capacitor compact"
  rect 0.8x1 smd paste-0.025 mask+0.07: 1(-0.725,0) 2(0.725,0)
  silkscreen extent -0.1,-0.4 0.1,0.4, body extent -0.8,-0.4 0.8,0.4, height 0.83
CC0805 [mm] "MLCCeramic 0805 Density B"
  rect 1x1.32 smd paste-0.025 mask+0.07: 1(-0.975,0) 2(0.975,0)
  silkscreen extent -0.25,-0.63 0.25,0.63, body extent -1,-0.63 1,0.63, height 1.28
D0298T34M [mm] "EPC2059"
  rrect50% 0.321x0.546 smd paste-1 mask-1: 1(-1.2,0.387) 2(-1.2,-0.387)
  rrect50% 0.321x1.081 smd paste-1 mask-1: 3(-0.6,0) 5(0.6,0)
  rrect50% 0.321x1.321 smd paste-1 mask-1: 4(0,0) 6(1.2,0)
  rrect50% 0.25x0.475 on Top Paste paste-1 mask-1: ""(-1.2,-0.387) ""(-1.2,0.387)
  rrect75% 0.25x0.475 on Top Solder paste-1 mask-1: ""(-1.2,-0.387) ""(-1.2,0.387)
  rrect75% 0.25x1.01 on Top Solder paste-1 mask-1: ""(-0.6,0) ""(0.6,0)
  rrect50% 0.25x1.01 on Top Paste paste-1 mask-1: ""(-0.6,0) ""(0.6,0)
  rrect75% 0.25x1.25 on Top Solder paste-1 mask-1: ""(0,0) ""(1.2,0)
  rrect50% 0.25x1.25 on Top Paste paste-1 mask-1: ""(0,0) ""(1.2,0)
  silkscreen extent -1.51,-0.8 1.5,0.86, body extent -1.4,-0.7 1.4,0.7, height 0.64
D0606_100V [mm] "EPC2301"
  rrect20% 1.091x1.15 smd paste-1 mask-1: 1(-2.321,1.222)
  rrect20% 1.091x2.29 smd paste-1 mask-1: 2(-2.321,-0.658)
  rrect20% 0.7x3.6 smd paste-1 mask-1: 3(-1.275,0) 4(-0.425,0) 5(0.425,0) 6(1.275,0)
  rrect20% 1.091x3.6 smd paste-1 mask-1: 7(2.321,0)
  rrect25% 0.7x0.37 on Top Solder paste-1 mask-1: ""(-2.351,-0.975) ""(-2.351,-0.325) ""(-2.351,0.975) ""(2.351,-0.975) ""(2.351,-0.325) ""(2.351,0.325) ""(2.351,0.975)
  rrect25% 0.76x0.37 on Top Solder paste-1 mask-1: ""(-2.321,0.225)
  rrect50% 0.65x2 on Top Paste paste-1 mask-1: ""(-2.31,-0.64)
  rrect50% 0.6x0.875 on Top Paste paste-1 mask-1: ""(-2.31,1.237)
  rrect25% 0.47x2.075 on Top Solder paste-1 mask-1: ""(-2.175,-0.663)
  rrect25% 0.47x0.985 on Top Solder paste-1 mask-1: ""(-2.175,1.207)
  rrect25% 0.37x3.4 on Top Solder paste-1 mask-1: ""(-1.275,0) ""(-0.425,0) ""(0.425,0) ""(1.275,0)
  rrect50% 0.28x3.32 on Top Paste paste-1 mask-1: ""(-1.275,0) ""(-0.425,0) ""(0.425,0) ""(1.275,0)
  rrect25% 0.47x3.4 on Top Solder paste-1 mask-1: ""(2.175,0)
  rrect50% 0.61x3.32 on Top Paste paste-1 mask-1: ""(2.32,0)
  silkscreen extent -2.76,-1.66 2.75,1.7, body extent -2.5,-1.5 2.5,1.5, height 0.76
DFN1006-2 [mm]
  rect 0.4x0.7 smd paste-0.025 mask+0.07: A(0.35,0) K(-0.35,0)
  silkscreen extent -0.7,-0.35 -0.7,0.35, body extent -0.5,-0.3 0.5,0.3, height 0.51
Fiducial_Board [mil] "Small Fiducial"
  round 40 smd paste-20 mask+20: 0(0,0)
  round 40 smd far side paste-20 mask+20: 0(0,0)
  Mid-Layer 1 pour cut-out: 0,43.31 16.57,40.01 30.62,30.62 40.01,16.57 43.31,0 43.31,0 40.01,-16.57 30.62,-30.62 16.57,-40.01 0,-43.31 0,-43.31 -16.57,-40.01 -30.62,-30.62 -40.01,-16.57 -43.31,0 -43.31,0 -40.01,16.57 -30.62,30.62 -16.57,40.01 0,43.31
  Mid-Layer 6 pour cut-out: 0,43.31 16.57,40.01 30.62,30.62 40.01,16.57 43.31,0 43.31,0 40.01,-16.57 30.62,-30.62 16.57,-40.01 0,-43.31 0,-43.31 -16.57,-40.01 -30.62,-30.62 -40.01,-16.57 -43.31,0 -43.31,0 -40.01,16.57 -30.62,30.62 -16.57,40.01 0,43.31
  Bottom Layer pour cut-out: 0,43.31 16.57,40.01 30.62,30.62 40.01,16.57 43.31,0 43.31,0 40.01,-16.57 30.62,-30.62 16.57,-40.01 0,-43.31 0,-43.31 -16.57,-40.01 -30.62,-30.62 -40.01,-16.57 -43.31,0 -43.31,0 -40.01,16.57 -30.62,30.62 -16.57,40.01 0,43.31
  Multi-Layer pour cut-out: 0,43.31 16.57,40.01 30.62,30.62 40.01,16.57 43.31,0 43.31,0 40.01,-16.57 30.62,-30.62 16.57,-40.01 0,-43.31 0,-43.31 -16.57,-40.01 -30.62,-30.62 -40.01,-16.57 -43.31,0 -43.31,0 -40.01,16.57 -30.62,30.62 -16.57,40.01 0,43.31
Hot_SIGN [mm]
LC0402sml [mm]
  rect 0.4x0.6 smd paste-0.025 mask+0.025: 1(-0.45,0) 2(0.45,0)
  silkscreen extent -0.08,-0.25 0.08,0.25, body extent -0.5,-0.25 0.5,0.25, height 0.5
MSOP8 [mm]
  rect 0.4x1.35 smd paste-0.025 mask+0.07: 1(-0.975,-2.15) 2(-0.325,-2.15) 3(0.325,-2.15) 4(0.975,-2.15) 5(0.975,2.15) 6(0.325,2.15) 7(-0.325,2.15) 8(-0.975,2.15)
  silkscreen extent -1.73,-1.77 1.5,1.25, body extent -1.5,-2.45 1.5,2.45, height 0.95
POWERDI-123 [mm] "Improved cooling SOD123"
  rect 0.9x1.4 smd paste+0 mask+0.102: A(1.275,0)
  rect 2.2x1.4 smd paste+0 mask+0.102: K(-1.275,0)
  silkscreen extent -2.6,-1.02 0.87,1.02, body extent -2.27,-0.96 1.63,0.97, height 1.03
RC0402 [mm]
  rect 0.4x0.6 smd paste-0.025 mask+0.025: 1(-0.45,0) 2(0.45,0)
  silkscreen extent -0.13,-0.25 0.13,0.25, body extent -0.5,-0.25 0.5,0.25, height 0.38
RC1206 [mm] "MLCCeramic 1206 Density B"
  rect 1.15x1.8 smd paste-0.025 mask+0.07: 1(-1.5,0) 2(1.5,0)
  silkscreen extent -0.7,-0.8 0.7,0.8, body extent -1.6,-0.8 1.6,0.8, height 0.58
"TUMD2SM ROHM" [mm] "ROHM variation on SOD323F for higher current and voltage"
  rect 0.8x1.1 smd paste-0.05 mask+0.07: A(-1.15,0) K(1.15,0)
  silkscreen extent -0.6,-0.7 0.63,0.7, body extent -1.25,-0.7 1.25,0.7, height 0.71
WQFN-19 [mm] "300V HB Gate Driver"
  rrect50% 0.75x0.71 on Top Paste: 0(-0.475,0.975) 0(0.475,0.975)
  rrect50% 0.75x1.13 on Top Paste: 0(-0.475,-0.75) 0(0.475,-0.75)
  rrect40% 0.25x0.6 smd paste+0 mask+0.05: 1(-1,-1.925) 2(-0.5,-1.925) 3(0,-1.925) 4(0.5,-1.925) 5(1,-1.925) 11(1,1.925) 12(0.5,1.925) 13(0,1.925) 14(-0.5,1.925) 15(-1,1.925)
  rrect40% 0.6x0.25 smd paste+0 mask+0.05: 6(1.4,-1.25) 7(1.4,-0.75) 8(1.4,-0.25) 9(1.4,0.75) 10(1.4,1.25) 16(-1.4,1.25) 17(-1.4,-0.25) 18(-1.4,-0.75) 19(-1.4,-1.25)
  rrect15% 1.7x1.2 smd paste-1.7 mask+0.05: 20(0,-0.75)
  rrect15% 1.7x0.75 smd paste-1.5 mask+0.05: 21(0,0.975)
  silkscreen extent -2.07,-2.15 1.65,2.15, body extent -1.55,-2.07 1.55,2.07, height 0.82

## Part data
C10 C20 C30 C40: library part C0402-TBD, Case Size=0402, TempCo=TBD
C11 C21 C31 C41: library part C0402-220pF-100V-C0G-5%, Case Size=0402, EPC Part Number=C-0402-040, Supplier Part Number 1=445-15198-1-ND, TempCo=C0G/NP0, Tolerance=0.05, Voltage=100
C12 C22: library part C0402-470nF-25V-X5R-10%, Case Size=0402, EPC Part Number=C-0402-054, Supplier Part Number 1=445-8020-1-ND, TempCo=X5R, Tolerance=0.1, Voltage=25
C13 C23: library part C0402-1uF-25V-X5R-10%, Case Size=0402, EPC Part Number=C-0402-025, Supplier Part Number 1=445-9066-1-ND, TempCo=X5R, Tolerance=0.1, Voltage=25
C32 C33 C42 C43 C51 C52 C56 C62 C63 C64 C66 C67 C68 C70: library part C0402-2.2uF-25V-X5R-20%-Murata, Case Size=0402, Supplier Part Number 1=490-10457-1-ND, TempCo=X5R, Tolerance=0.2, Voltage=25
C50: library part C0402-47pF-50V-C0G/NP0-5%, Case Size=0402, EPC Part Number=C-0402-012, Supplier Part Number 1=311-1021-1-ND, TempCo=C0G/NP0, Tolerance=0.05, Voltage=50
C53 C54 C60 C61 C65 C69: library part C0603-10uF-25V-X5R-20%, Case Size=0603, Supplier Part Number 1=445-9015-1-ND, TempCo=X5R, Tolerance=0.2, Voltage=25
C80 C81 C82 C83 C84: library part C0805-1uF-100V-X7R-10%, Case Size=0805, EPC Part Number=C-0805-048, Supplier Part Number 1=478-12143-1-ND, TempCo=X7R, Tolerance=0.1, Voltage=100
D10 D20: library part DS-200V-1A-DFLS1200, Case Size=POWERDI-123, Current Rating=1A, EPC Part Number=D-009, Voltage Rating=200V
D50 D63 D64: library part D-80V-125mA-1N4448HLP-7, Case Size=DFN1006-2, Current Rating=125mA, Supplier Part Number 1=1N4448HLPDICT-ND, Voltage Rating=80V
D61 D62: library part D-600V-200mA-RFU02VSM6STR, Case Size="TUMD2SM ROHM", Current Rating=200mA, EPC Part Number=D-042, Voltage Rating=600V
FB50 FB60 FB61: library part FB0402_1.8kE_150mA_0402, Case Size=0402, Current Rating=150mA, Supplier Part Number 1=445-172716-1-ND, Tolerance=0.25
FD1 FD2 FD3: library part Fiducial_Board
LB2: library part Hot_Sign, "Hot Symbol"
Q1A Q1B Q2A Q2B Q3A Q3B Q4A Q4B: "100V 100A 1.9mE"
Q6: "170V 25A 9mE", Supplier Part Number 1=917-EPC2059CT-ND
R1A R1B R2A R2B R3A R3B R4A R4B R50 R51 R60 R61: library part R0402-2.2-1%-1/16W-Thickfilm, Case Size=0402, EPC Part Number=R-0402-016, Power Rating=1/16, Supplier Part Number 1=RMCF0402FT2R0CT-ND, Tolerance=0.01
R10 R20 R30 R40: library part R0402-10k-1%-0.1W-Thickfilm, Case Size=0402, EPC Part Number=R-0402-011, Power Rating=0.1, Supplier Part Number 1=P10.0KLCT-ND, Tolerance=0.01
R11 R13 R21 R23 R31 R33 R41 R43 R62 R63 R64 R65: library part R0402-0-0.1W, Case Size=0402, EPC Part Number=R-0402-004, Power Rating=0.1, Supplier Part Number 1=P0.0JCT-ND
R12 R22 R32 R42: library part R0402-100-1%-0.1W-Thickfilm, Case Size=0402, Power Rating=1/16, Supplier Part Number 1=311-100LRCT-ND, Tolerance=0.01
R52: library part R0402-5.6-5%-0.1W-ThickFilm, Case Size=0402, Power Rating=0.1, Supplier Part Number 1=10-ERJ-U02J5R6XCT-ND, Tolerance=0.05
R80: library part R1206-TBD, Case Size=1206
S2: "Anti-static caution sign"
SO1 SO2 SO3 SO4 SO6: library part EPC_SMD_Thermal_SpacerM2x1mm
U1 U3 U5: "Digittal Isolator,150Mbps, 6KV, 10nS Delay MSOP"
U2 U4: library part LMG1210RVRT, EPC Part Number=IC-109, Supplier Part Number 1=296-53417-2-ND, Voltage Rating=300
U6: library part UCC27611DRVT, EPC Part Number=IC-004, Supplier Part Number 1=296-35639-2-ND

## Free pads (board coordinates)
  rect 0.635x3 smd: 2(1.917,1.8) 2(3.117,1.8) 2(4.317,1.8) 2(5.517,1.8) 2(6.717,1.8) 2(7.918,1.8) 2(9.118,1.8)
  rect 0.635x3 smd far side: 2(1.917,1.8) 2(3.117,1.8) 2(4.317,1.8) 2(5.517,1.8) 2(6.717,1.8) 2(7.918,1.8) 2(9.118,1.8)
  round 0.75 smd far side paste-0.75 mask+0: 3(4.328,19.179)
  oval 2x1.524 / inner round 1.524 / far side oval 2x1.524 hole 1.016 paste+0 mask+0.05: 4(1.3,12.587)
  oval 2x1.524 / inner round 1.524 / far side oval 2x1.524 hole 1.016 paste+0.5 mask+0.05: 4(1.3,15.127)

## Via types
v1: diameter 0.508, hole 0.254, Top Layer to Bottom Layer, tented both sides, 565 vias
v2: diameter 0.508, hole 0.254, Top Layer to Bottom Layer, 32 vias

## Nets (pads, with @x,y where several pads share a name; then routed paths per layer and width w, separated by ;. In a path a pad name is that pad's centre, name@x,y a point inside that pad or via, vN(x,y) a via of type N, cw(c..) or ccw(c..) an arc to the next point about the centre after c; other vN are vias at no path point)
12V: C53.2 C60.2 C61.1 FB60.1 FB61.1 R50.1 R61.2 | length 40
  Bottom Layer w0.254: C60.2@6.883,10.306 6.883,9.114 C61.1@6.89,9.108 C61.1@6.89,9.008 ; C53.2@19.2,7.925 C53.2@19.3,7.925
  Bottom Layer w0.4: R61.2@3.15,7.003 4.886,7.003 6.89,9.008 8.504,7.393 18.568,7.393 19.1,7.925 C53.2@19.2,7.925 R50.1@19.2,8.745 ; C53.2@19.3,7.925 19.832,7.393 20.144,7.393 FB61.1@39.044,7.29
ACL_DRV: U5.7 U6.3 | length 2.7
  Top Layer w0.254: v1(24.673,8.4) U6.3@24.673,9.1
  Bottom Layer w0.254: U5.7@24.496,10.285 24.496,8.645 24.673,8.469 v1(24.673,8.4)
BOOT5V: C52.1 C56.2 U5.8 U6.6 | length 5.7
  Top Layer w0.254: C56.2@22.474,11.1 23.35,11.1 23.373,11.123 U6.6@23.373,11.2
  Bottom Layer w0.254: v1(22.474,11.072) 23.148,11.746 23.148,12.059 23.301,12.212 24.048,12.212 24.51,11.75 C52.1@24.51,11.65 24.51,11.55 24.583,11.477 24.819,11.477 25.126,11.17 25.126,10.306 U5.8@25.146,10.285
BOOT12V: C54.2 D50.K U6.1 | length 3.7
  Top Layer w0.254: v1(21.842,9.216) 21.911,9.216 22.027,9.1 U6.1@23.373,9.1
  Bottom Layer w0.254: v1(21.842,9.216) C54.2@21.842,9.292
  Bottom Layer w0.4: D50.K@21.443,11.15 21.443,9.691 C54.2@21.842,9.292
GateHSA: R1A.1 R1B.1 U2.10 | length 13.5
  Top Layer w0.254: 11.846,15.725 12,15.571 U2.10@12,15.4
  Top Layer w0.5: 11.846,15.725 v1(11.846,16.2)
  Bottom Layer w0.6: R1A.1@5.178,17.95 9.902,17.95 ; v1(11.846,16.2) 11.682,16.364 10.4,16.364 9.902,16.862 9.902,17.95 ; R1B.1@14.483,17.95 9.902,17.95
GateHSB: R2A.1 R2B.1 U4.10 | length 13.7
  Top Layer w0.254: 34.251,15.696 34.376,15.571 U4.10@34.376,15.4
  Top Layer w0.5: 34.251,15.696 34.251,16.183 34.266,16.198 v1(34.266,16.2)
  Bottom Layer w0.6: R2A.1@27.45,17.9 27.5,17.85 32.102,17.85 ; v1(34.266,16.2) 34.011,16.455 32.469,16.455 32.102,16.821 32.102,17.85 ; R2B.1@36.819,17.9 36.769,17.85 32.102,17.85
GateLSA: R3A.1 R3B.1 U2.8 | length 13.6
  Top Layer w0.254: U2.8@13.395,15.669 13.495,15.569 13.498,15.569 13.5,15.567 U2.8@13.5,15.4
  Top Layer w0.5: U2.8@13.395,15.669 13.395,16.513
  Top Layer w0.6: R3A.1@10.796,17.927 15.531,17.927 ; 13.426,16.556 13.919,17.049 15.531,17.049 15.531,17.927 ; R3B.1@20.08,17.927 15.531,17.927
GateLSB: R4A.1 R4B.1 U4.8 | length 13.3
  Top Layer w0.254: 35.751,15.845 35.876,15.72 U4.8@35.876,15.4 ; 37.698,17.9 37.725,17.873
  Top Layer w0.5: 35.751,15.845 35.751,16.487
  Top Layer w0.6: R4A.1@33.05,17.9 37.698,17.9 R4B.1@42.347,17.9 ; 35.751,16.487 36.259,16.994 37.373,16.994 37.725,17.346 37.725,17.873
GND1: C11.2 C31.2 C64.2 R62.1 R64.2 U1.5 U2.3 U2.5 | length 12.1
  Top Layer w0.254: v1(12.796,9.2) 12.799,9.198 12.799,7.591 R64.2@12.801,7.588 ; C11.2@13.807,10.616 C11.2@13.814,10.608 ; U2.3@15.175,14 15.177,14.002 R62.1@15.756,14.002 ; v1(15.756,14.034) R62.1@15.756,14.002 ; R62.1@15.817,14.007 15.812,14.002 R62.1@15.756,14.002
  Top Layer w0.4: C11.2@13.807,10.616 C11.2@13.907,10.616 ; C11.2@14.086,10.436 v1(14.107,10.416) 13.922,10.6 C31.2@14.644,10.6
  Bottom Layer w0.254: v1(12.796,9.2) 12.869,9.273 12.869,9.884 13.397,10.412 13.823,10.412 13.896,10.485 C64.2@13.896,10.585 ; v1(14.107,10.416) 14.091,10.431 C64.2@14.091,10.6 ; v1(15.031,15.125) 14.982,15.076 14.982,14.627 14.723,14.368 14.723,14.009 ; v1(15.756,14.034) 15.731,14.009 14.723,14.009 ; C64.2@13.896,10.585 13.927,10.616 v1@14.107,10.616 ; C64.2@13.896,10.585 13.912,10.6 C64.2@14.091,10.6 ; C64.2@14.091,10.6 v1@14.107,10.616 ; v1@14.107,10.616 14.107,10.684 14.218,10.796 14.218,12.842 14.723,13.347 14.723,14.009
GND2: C21.2 C41.2 C68.2 R63.1 R65.2 U3.5 U4.3 U4.5 | length 11
  Top Layer w0.254: v1(35.616,9.2) 35.621,9.195 35.621,7.581 R65.2@35.626,7.576 ; U4.3@37.551,14 R63.1@38.274,14 ; R63.1@38.169,14 v1(38.169,14.002)
  Top Layer w0.3: C21.2@36.2,10.616 C41.2@36.95,10.616
  Bottom Layer w0.254: U3.5@35.619,9.2 35.692,9.273 35.692,9.869 36.235,10.412 36.596,10.412 36.669,10.485 C68.2@36.669,10.519 ; v1(36.65,10.5) C68.2@36.669,10.519 ; v1(37.389,15.124) 37.341,15.075 37.341,14.542 37.167,14.368 37.167,14.009 ; v1(38.169,14.002) 38.162,14.009 37.167,14.009 ; C68.2@36.669,10.519 C68.2@36.669,10.585 36.685,10.601 36.685,13.527 37.167,14.009
HSD1: C10.1 R11.2 R13.1 U1.3 | length 2
  Top Layer w0.254: C10.1@13.363,5.892 13.422,5.951 13.422,6.573 13.525,6.676 R13.1@13.625,6.676 ; v1(13.407,5.592) 13.422,5.576 13.422,4.72 R11.2@13.438,4.705 R11.2@13.438,4.805
HSD2: C20.1 R21.2 R23.1 U3.3 | length 2.1
  Top Layer w0.254: R21.2@36.4,5.005 36.408,5.013 36.408,5.784 C20.1@36.417,5.792 36.395,5.814 36.395,6.654 R23.1@36.373,6.676 36.45,6.676 R23.1@36.523,6.603 ; R21.2@36.417,5.072 36.484,5.005 R21.2@36.484,5.105
  other v1: 36.226,5.005
I-HSD1: R12.1 R13.2 U1.6 | length 3.3
  Top Layer w0.254: R12.1@12.988,10.616 13.02,10.584 13.02,10.13 13.438,9.711 v1(13.438,9.65) 13.438,9.581 13.625,9.394 R13.2@13.625,7.576
I-HSD2: R22.1 R23.2 U3.6 | length 3.5
  Top Layer w0.254: R22.1@35.476,10.616 35.526,10.616 35.593,10.549 35.593,10.352 36.266,9.68 v1(36.266,8.8) 36.266,7.649 36.339,7.576 R23.2@36.373,7.576
I-LSD1: R32.1 R33.2 U1.7 | length 4
  Top Layer w0.254: R33.2@14.476,7.6 R33.2@14.5,7.576 14.5,9.216 14.135,9.581 v1(14.135,9.65) 14.154,9.668 14.77,9.668 15.252,10.15 15.252,10.351 15.325,10.424 R32.1@15.425,10.424
I-LSD2: R42.1 R43.2 U3.7 | length 3.6
  Top Layer w0.254: v1@36.908,9.65 36.935,9.623 36.935,7.776 36.962,7.749 36.962,7.649 37.035,7.576 R43.2@37.135,7.576 ; v1(36.929,9.65) 37.532,10.253 37.532,10.543 37.605,10.616 R42.1@37.698,10.616
LSD1: C30.1 R31.2 R33.1 U1.2 | length 1.9
  Top Layer w0.254: R31.2@14.11,4.705 14.123,4.717 14.123,5.579 v1(14.135,5.592) ; C30.1@14.203,5.892 14.276,5.965 14.276,6.552 14.4,6.676 R33.1@14.5,6.676 R33.1@14.478,6.654
LSD2: C40.1 R41.2 R43.1 U3.2 | length 2.3
  Top Layer w0.254: v1(36.959,4.556) 36.959,5.497 37.009,5.547 37.009,5.827 C40.1@37.04,5.858 ; C40.1@37.016,5.985 37.135,6.103 R43.1@37.135,6.676 ; C40.1@37.082,5.633 37.082,5.742 C40.1@37.082,5.819
NetC11_1: C11.1 R12.2 U2.18 | length 2
  Top Layer w0.254: R12.2@12.988,11.516 C11.1@13.807,11.516 13.907,11.516 14,11.609 U2.18@14,12.6
NetC12_1: C12.1 C13.1 D10.K U2.12 | length 1.7
  Top Layer w0.254: C13.1@9.673,14.446 C12.1@10.431,14.446 10.483,14.498 11.323,14.498 U2.12@11.325,14.5
  other v1: 9.673,14.447
NetC21_1: C21.1 R22.2 U4.18 | length 1.9
  Top Layer w0.254: R22.2@35.476,11.516 C21.1@36.2,11.516 36.3,11.516 36.376,11.592 U4.18@36.376,12.6
NetC22_1: C22.1 C23.1 D20.K U4.12 | length 1.8
  Top Layer w0.254: v1(31.95,14.575) 31.95,14.545 C23.1@32,14.495 C22.1@32.84,14.495 32.843,14.498 33.699,14.498 U4.12@33.701,14.5
NetC31_1: C31.1 R32.2 U2.19 | length 2.1
  Top Layer w0.254: U2.19@14.5,12.6 14.5,11.573 14.573,11.5 C31.1@14.644,11.5 14.717,11.427 15.222,11.427 15.325,11.324 R32.2@15.425,11.324
NetC41_1: C41.1 R42.2 U4.19 | length 1.8
  Top Layer w0.254: U4.19@36.876,12.6 36.876,11.589 C41.1@36.95,11.516 R42.2@37.678,11.516
NetC50_1: C50.1 R51.2 U5.2 | length 0.9
  Top Layer w0.254: C50.1@24.438,5.218 24.438,6.045 v1(24.496,6.103)
NetC80_1: C80.1 C81.1 C82.1 C83.1 C84.1 Q6.3 Q6.5 R80.1 | length 0.2
  Bottom Layer w0.254: C84.1@27.025,8.4 C84.1@27.136,8.289
  other v1: 27.101,8.2 27.101,9.1 27.024,13.625 27.024,14.223 27.024,14.875 27.024,15.49 27.024,16.09
NetD10_A: D10.A U2.17 | length 4.5
  Top Layer w0.254: 12.338,11.41 12.338,11.736 12.596,11.994 13.223,11.994 13.498,12.269 13.498,12.598 U2.17@13.5,12.6
  Top Layer w0.4: v1(10.002,11.052) 11.98,11.052 12.338,11.41
NetD20_A: D20.A U4.17 | length 4.3
  Top Layer w0.254: 33.875,11.055 34.109,11.055 34.858,11.804 34.858,11.83 35.012,11.984 35.038,11.984 35.106,12.052 35.571,12.052 35.876,12.357 U4.17@35.876,12.6
  Top Layer w0.4: v1(32.395,11.055) 33.875,11.055
NetD50_A: D50.A FB50.2 | length 0.6
  Bottom Layer w0.4: FB50.2@20.182,11.15 D50.A@20.743,11.15
NetD61_A: D61.A FB60.2 | length 0.7
  Bottom Layer w0.254: D61.A@16.633,8.98 D61.A@16.655,8.958
  Bottom Layer w0.4: FB60.2@16.655,8.305 D61.A@16.655,8.958
NetD62_A: D62.A FB61.2 | length 0.7
  Bottom Layer w0.254: D62.A@39.044,8.833 D62.A@39.06,8.85
  Bottom Layer w0.4: FB61.2@39.044,8.19 D62.A@39.044,8.833
NetD63_K: D63.K D64.A | length 0.6
  Bottom Layer w0.254: D63.K@4.986,5.25 D64.A@5.592,5.25
NetFB50_1: FB50.1 R50.2 | length 1.5
  Bottom Layer w0.254: R50.2@19.2,9.645 19.209,9.645 R50.2@19.282,9.718
  Bottom Layer w0.4: R50.2@19.282,9.718 FB50.1@19.282,11.15
NetQ1A_1: pad.3 Q1A.1 R1A.2 | length 1.2
  Bottom Layer w0.254: R1A.2@4.278,17.95 R1A.2@4.303,17.975 ; pad.3@4.303,19.154 v1(4.328,19.179)
  Bottom Layer w0.6: R1A.2@4.303,17.975 pad.3@4.303,19.154
NetQ1B_1: Q1B.1 R1B.2 | length 1.2
  Bottom Layer w0.254: v1(15.438,19.179) v1@15.442,19.175 ; R1B.2@15.442,17.954 R1B.2@15.446,17.95
  Bottom Layer w0.6: R1B.2@15.442,17.954 v1@15.442,19.175
NetQ2A_1: Q2A.1 R2A.2 | length 1.4
  Bottom Layer w0.254: R2A.2@26.55,17.9 R2A.2@26.561,17.911 ; v1@26.561,19.245 v1(26.572,19.256)
  Bottom Layer w0.6: R2A.2@26.561,17.911 v1@26.561,19.245
NetQ2B_1: Q2B.1 R2B.2 | length 1.3
  Bottom Layer w0.6: R2B.2@37.719,17.9 v1(37.719,19.208)
NetQ3A_1: Q3A.1 R3A.2 | length 1.3
  Top Layer w0.254: Q3A.1@9.888,19.179 Q3A.1@9.896,19.171
  Top Layer w0.5: R3A.2@9.896,17.927 Q3A.1@9.896,19.171
NetQ3B_1: Q3B.1 R3B.2 | length 1.3
  Top Layer w0.254: Q3B.1@20.979,19.16 Q3B.1@20.998,19.179
  Top Layer w0.5: R3B.2@20.979,17.927 Q3B.1@20.979,19.16
NetQ4A_1: Q4A.1 R4A.2 | length 1.3
  Top Layer w0.254: Q4A.1@32.118,19.179 Q4A.1@32.15,19.147
  Top Layer w0.6: R4A.2@32.15,17.9 Q4A.1@32.15,19.147
NetQ4B_1: Q4B.1 R4B.2 | length 1.3
  Top Layer w0.254: Q4B.1@43.238,19.179 Q4B.1@43.247,19.17 ; R4B.2@43.247,17.95 R4B.2@43.299,17.897
  Top Layer w0.6: R4B.2@43.247,17.95 Q4B.1@43.247,19.17
NetQ6_1: Q6.1 R52.1 U6.4 | length 3.2
  Top Layer w0.254: R52.1@24.03,12.952 24.652,12.952 24.673,12.973 ; U6.4@24.673,11.2 24.673,12.973 ; Q6.1@24.763,13.69 24.707,13.69 24.673,13.656 24.673,12.973
NetR52_2: R52.2 U6.5 | length 0.9
  Top Layer w0.254: U6.5@24.023,11.2 24.026,11.203 24.026,12.049 R52.2@24.03,12.052
NetR60_2: R60.2 R61.1 | length 0.5
  Bottom Layer w0.4: R60.2@3.15,5.554 R61.1@3.15,6.103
